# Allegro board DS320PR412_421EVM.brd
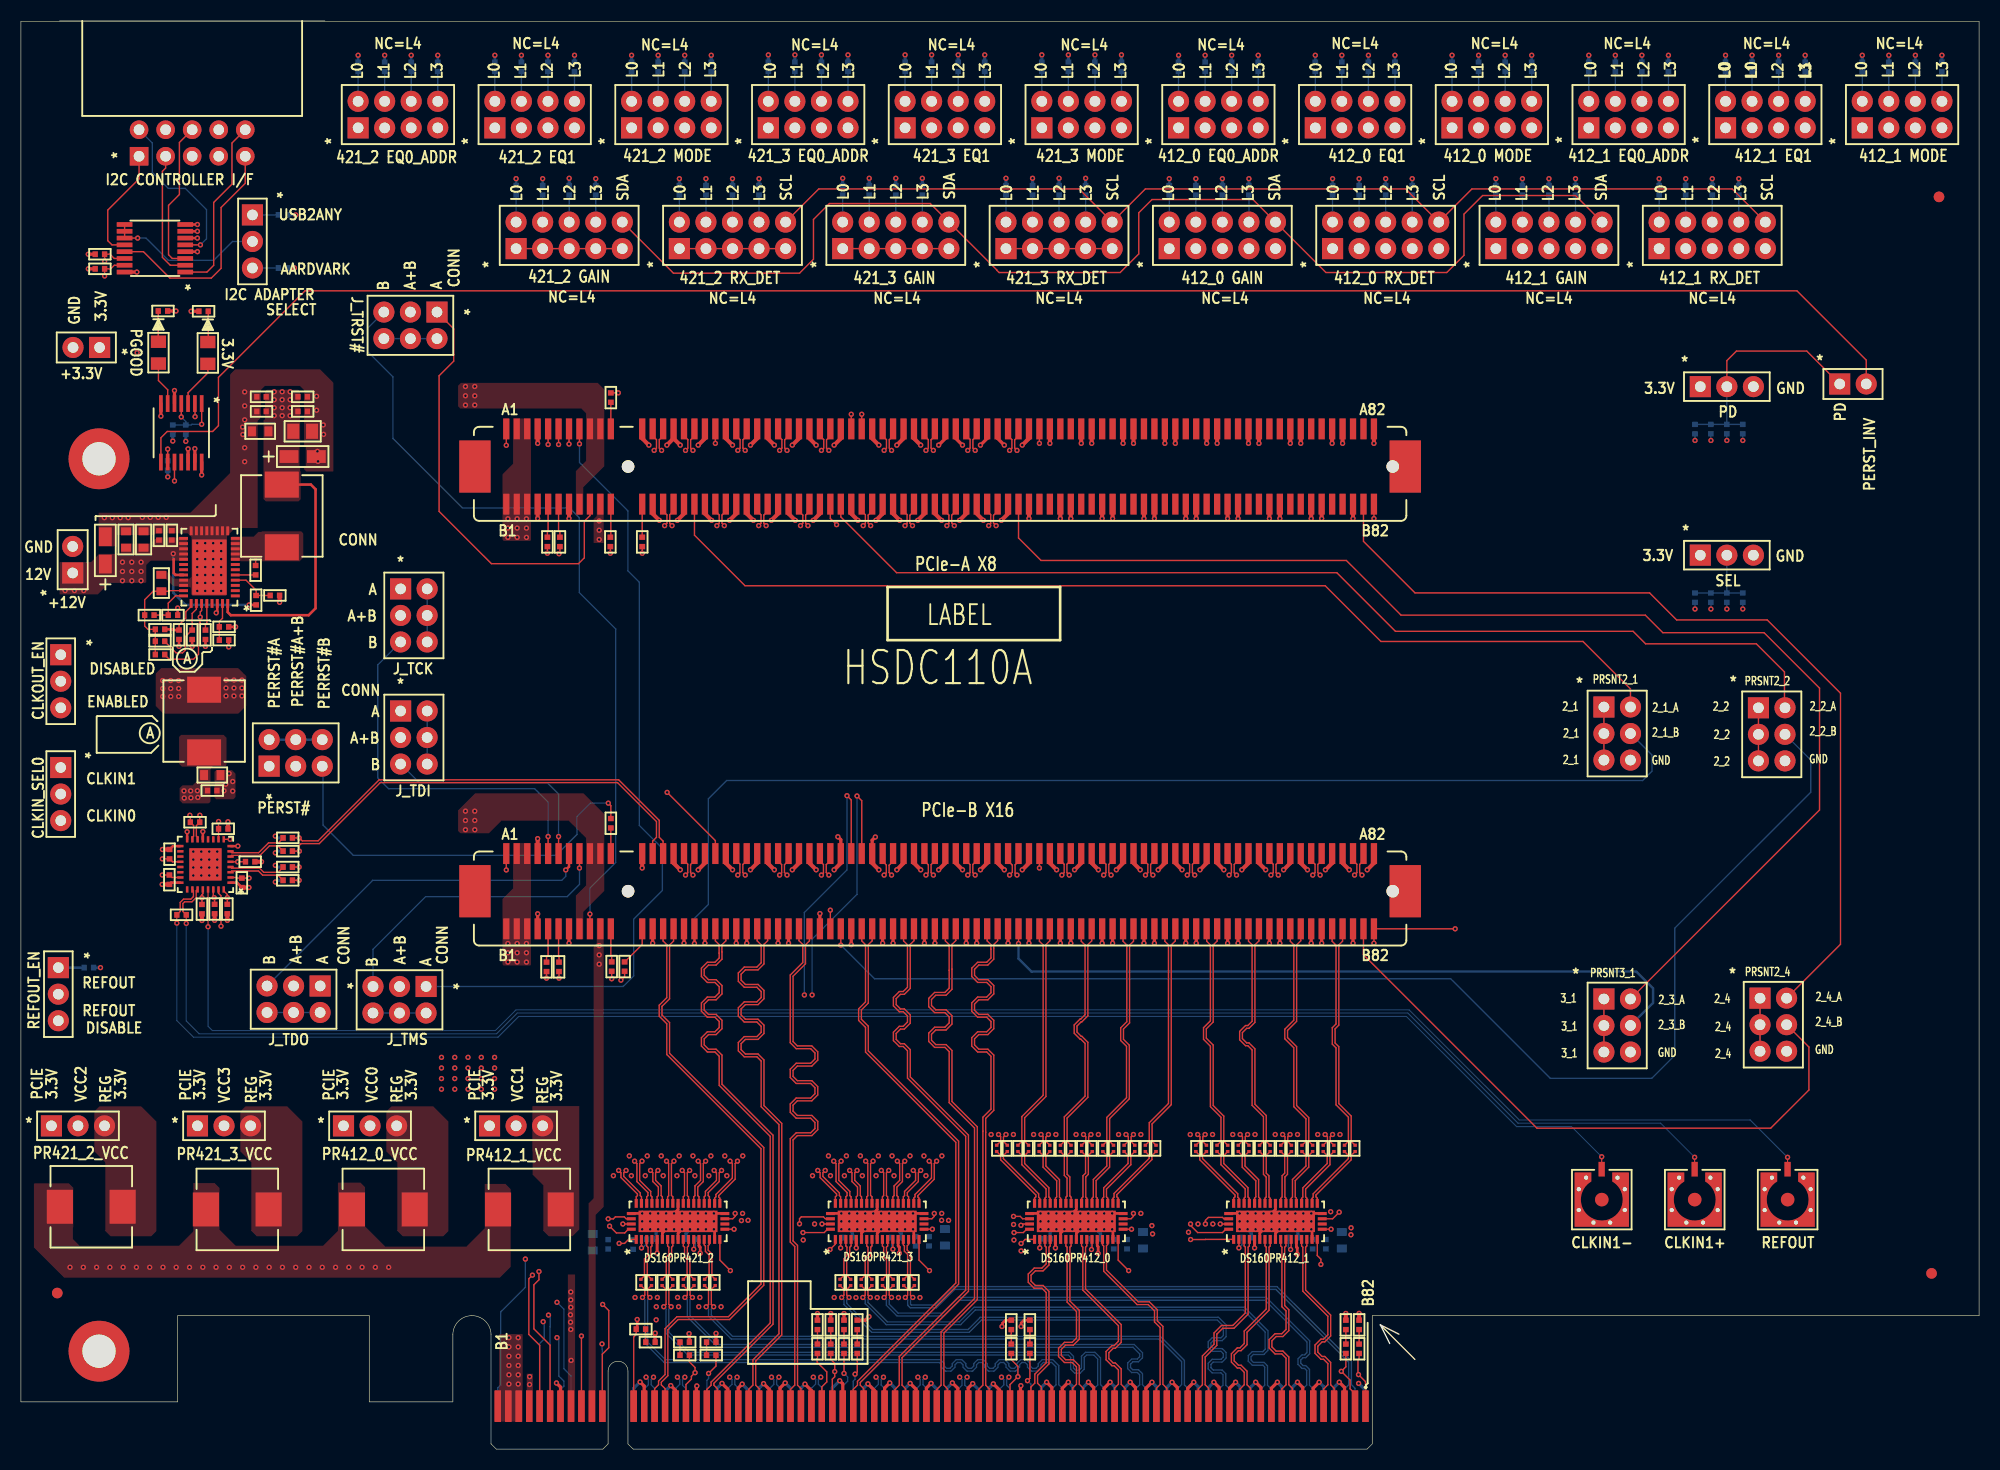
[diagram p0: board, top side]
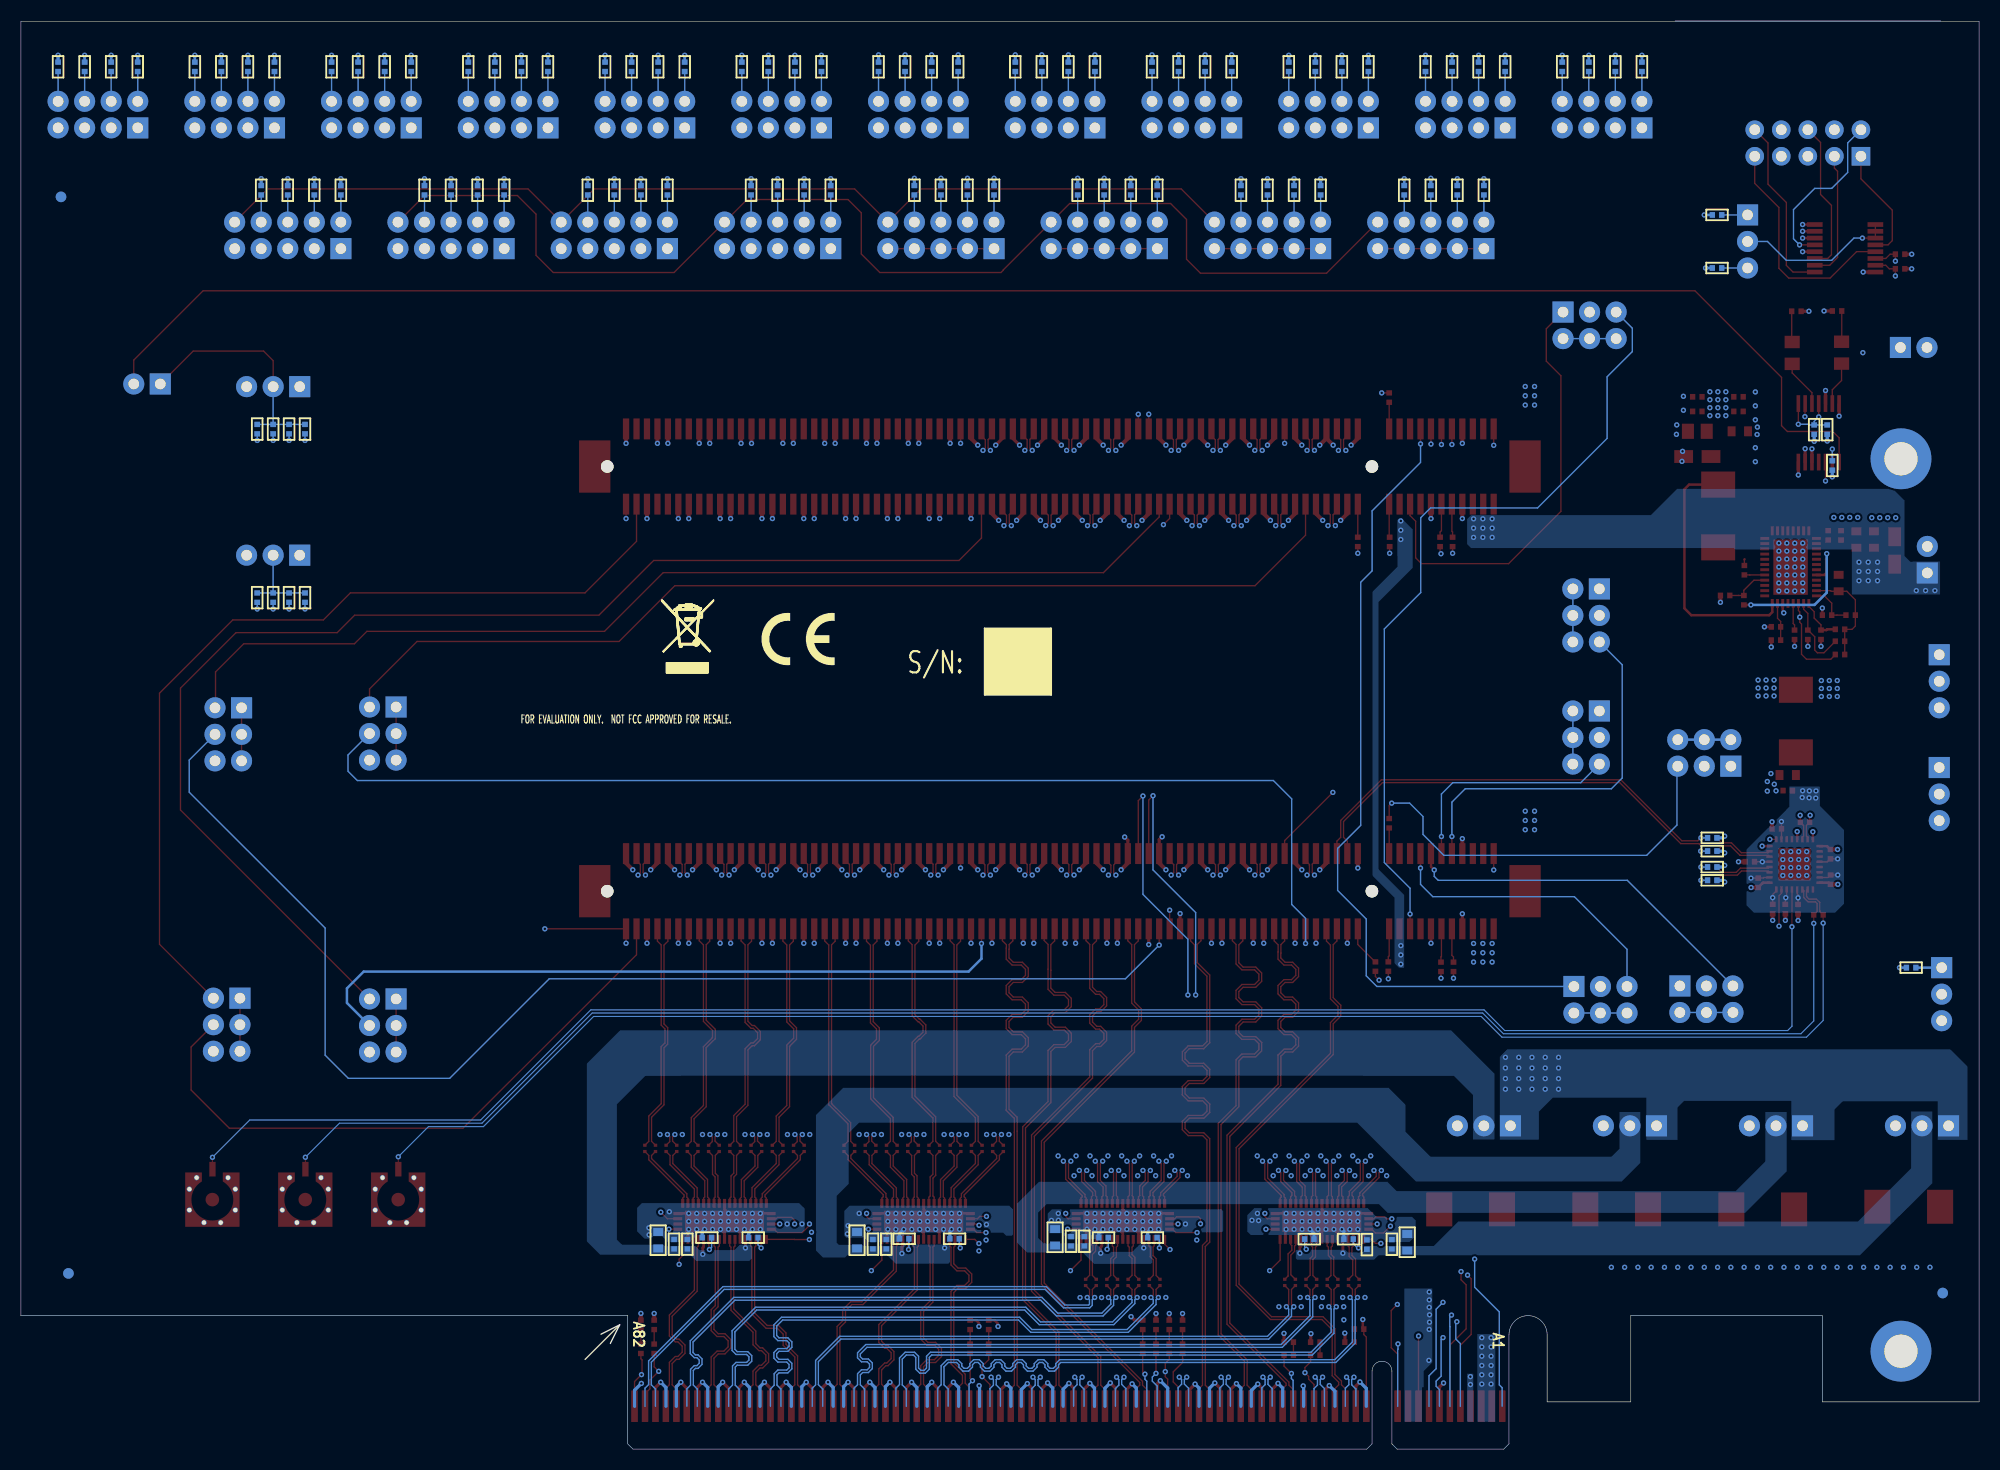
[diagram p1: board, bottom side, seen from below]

Outline 187.32 x 136.68 mm; copper layers: TOP, L2_GND, L3_SIG, L4_SIG, L5_GND, BOTTOM. Coordinates in mm from the lower left corner of the outline.
Outline path: 0,136.63 187.32,136.63 187.32,12.77 129.27,12.77 129.27,0.5 128.77,0 58.57,0 58.07,0.5 58.07,7.47 arc(57.12,8.42) 56.17,7.47 56.17,0.5 55.67,0 45.47,0 44.97,0.5 44.97,10.95 arc(44.44,12.24) 43.15,12.77 arc(41.86,12.24) 41.32,10.95 41.32,4.52 33.32,4.52 33.32,12.77 15,12.77 15,4.52 0,4.52 0,136.63

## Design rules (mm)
constraint set DEFAULT: min track width 0.102
net group DIFFPAIR3: nets PET9_N_B PET9_P_B
net group DIFFPAIR4: nets PER8_N PER8_P
net group DIFFPAIR5: nets PER9_N PER9_P
net group DIFFPAIR6: nets PER10_N PER10_P
net group DIFFPAIR7: nets PER11_N PER11_P
net group DIFFPAIR8: nets PER12_N PER12_P
net group DIFFPAIR9: nets PER13_N PER13_P
net group DIFFPAIR10: nets PER14_N PER14_P
net group DIFFPAIR11: nets PER15_N PER15_P
net group DIFFPAIR12: nets N16641538 N16641618
net group DIFFPAIR13: nets N16641774 N16641854
net group DIFFPAIR14: nets N16641982 N16642062
net group DIFFPAIR15: nets N16642250 N16642330
net group DIFFPAIR16: nets N16641526 N16641606
net group DIFFPAIR17: nets N16641762 N16641842
net group DIFFPAIR18: nets N16641970 N16642050
net group DIFFPAIR19: nets N16642238 N16642318
net group DIFFPAIR20: nets N16637226 N16637298
net group DIFFPAIR21: nets N16637382 N16637494
net group DIFFPAIR22: nets N16637572 N16637646
net group DIFFPAIR23: nets N16637738 N16637818
net group DIFFPAIR24: nets N16637946 N16638026
net group DIFFPAIR25: nets N16638098 N16638172
net group DIFFPAIR26: nets N16638286 N16638374
net group DIFFPAIR27: nets N16638446 N16638538
net group DIFFPAIR28: nets N16637238 N16637314
net group DIFFPAIR29: nets N16637394 N16637506
net group DIFFPAIR30: nets N16637586 N16637662
net group DIFFPAIR31: nets N16637750 N16637830
net group DIFFPAIR32: nets N16637958 N16638038
net group DIFFPAIR33: nets N16638114 N16638186
net group DIFFPAIR34: nets N16638298 N16638386
net group DIFFPAIR35: nets N16638462 N16638550
net group PET0_A: nets PET0_N_A PET0_P_A
net group PET1_A: nets PET1_N_A PET1_P_A
net group PET2_A: nets PET2_N_A PET2_P_A
net group PET3_A: nets PET3_N_A PET3_P_A
net group PET4_A: nets PET4_N_A PET4_P_A
net group PET5_A: nets PET5_N_A PET5_P_A
net group PET6_A: nets PET6_N_A PET6_P_A
net group PET7_A: nets PET7_N_A PET7_P_A
net group PET8_B: nets PET8_N_B PET8_P_B
net group PET10_B: nets PET10_N_B PET10_P_B
net group PET11_B: nets PET11_N_B PET11_P_B
net group PET12_B: nets PET12_N_B PET12_P_B
net group PET13_B: nets PET13_N_B PET13_P_B
net group PET14_B: nets PET14_N_B PET14_P_B
net group PET15_B: nets PET15_N_B PET15_P_B

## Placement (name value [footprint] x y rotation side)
C1  0.1uF  [CAP_0402]  98.01 20.13 180 bottom
C2  0.1uF  [CAP_0402]  102.83 20.13 180 bottom
C3  0.22uF  [CAP_0201]  93.34 28.78 90 top
C4  0.22uF  [CAP_0201]  94.36 28.78 90 top
C5  0.22uF  [CAP_0201]  95.38 28.78 90 top
C6  0.22uF  [CAP_0201]  96.39 28.78 90 top
C7  0.22uF  [CAP_0201]  97.41 28.78 90 top
C8  0.22uF  [CAP_0201]  98.42 28.78 90 top
C9  0.22uF  [CAP_0201]  99.44 28.78 90 top
C10  0.22uF  [CAP_0201]  100.46 28.78 90 top
C11  0.22uF  [CAP_0201]  101.47 28.78 90 top
C12  0.22uF  [CAP_0201]  102.49 28.78 90 top
C13  0.22uF  [CAP_0201]  103.5 28.78 90 top
C14  0.22uF  [CAP_0201]  104.52 28.78 90 top
C15  0.22uF  [CAP_0201]  105.54 28.78 90 top
C16  0.22uF  [CAP_0201]  106.55 28.78 90 top
C17  0.22uF  [CAP_0201]  107.57 28.78 90 top
C18  0.22uF  [CAP_0201]  108.58 28.78 90 top
C19  0.22uF  [CAP_0201]  112.39 28.78 90 top
C20  0.22uF  [CAP_0201]  113.41 28.78 90 top
C21  0.22uF  [CAP_0201]  114.43 28.78 90 top
C22  0.1uF  [CAP_0402]  117.26 20.24 180 bottom
C23  0.22uF  [CAP_0201]  115.44 28.78 90 top
C24  0.22uF  [CAP_0201]  116.46 28.78 90 top
C25  0.22uF  [CAP_0201]  117.47 28.78 90 top
C26  0.22uF  [CAP_0201]  118.49 28.78 90 top
C27  0.22uF  [CAP_0201]  119.51 28.78 90 top
C28  0.22uF  [CAP_0201]  120.52 28.78 90 top
C29  0.22uF  [CAP_0201]  121.54 28.78 90 top
C30  0.22uF  [CAP_0201]  122.56 28.78 90 top
C31  0.22uF  [CAP_0201]  123.57 28.78 90 top
C32  0.1uF  [CAP_0402]  121.7 20.24 180 bottom
C33  0.22uF  [CAP_0201]  124.59 28.78 90 top
C34  0.22uF  [CAP_0201]  125.6 28.78 90 top
C35  0.22uF  [CAP_0201]  126.62 28.78 90 top
C36  0.22uF  [CAP_0201]  127.64 28.78 90 top
C37  10uF  [CAP_0603]  107.34 19.99 270 bottom
C38  0.1uF  [CAP_0402]  104.55 19.61 270 bottom
C39  0.1uF  [CAP_0402]  105.82 19.61 270 bottom
C40  10uF  [CAP_0603]  126.36 19.99 270 bottom
C41  0.1uF  [CAP_0402]  123.57 19.61 270 bottom
C42  0.1uF  [CAP_0402]  124.84 19.61 270 bottom
C43  0.1uF  [CAP_0402]  60.32 20.09 0 bottom
C44  0.22uF  [CAP_0201]  59.31 15.95 90 top
C45  0.22uF  [CAP_0201]  60.33 15.95 90 top
C46  0.22uF  [CAP_0201]  61.34 15.95 90 top
C47  0.22uF  [CAP_0201]  62.36 15.95 90 top
C48  0.22uF  [CAP_0201]  63.37 15.95 90 top
C49  0.22uF  [CAP_0201]  64.39 15.95 90 top
C50  0.1uF  [CAP_0402]  64.07 20.09 180 bottom
C51  0.22uF  [CAP_0201]  65.41 15.95 90 top
C52  0.22uF  [CAP_0201]  66.42 15.95 90 top
C53  0.1uF  [CAP_0402]  79.09 20.24 0 bottom
C54  0.22uF  [CAP_0201]  78.36 15.95 90 top
C55  0.22uF  [CAP_0201]  79.38 15.95 90 top
C56  0.22uF  [CAP_0201]  80.39 15.95 90 top
C57  0.22uF  [CAP_0201]  81.41 15.95 90 top
C58  0.22uF  [CAP_0201]  82.42 15.95 90 top
C59  0.22uF  [CAP_0201]  83.44 15.95 90 top
C60  0.1uF  [CAP_0402]  83.76 20.24 0 bottom
C61  0.22uF  [CAP_0201]  84.45 15.95 90 top
C62  0.22uF  [CAP_0201]  85.47 15.95 90 top
C63  10uF  [CAP_0603]  54.71 19.8 270 bottom
C64  0.1uF  [CAP_0402]  58.56 19.57 270 bottom
C65  0.1uF  [CAP_0402]  56.17 19.6 270 bottom
C66  10uF  [CAP_0603]  88.39 20.27 270 bottom
C67  0.1uF  [CAP_0402]  86.87 19.89 270 bottom
C68  0.1uF  [CAP_0402]  85.6 19.89 270 bottom
C69  0.1uF  [CAP_0402]  22.45 84.11 90 top
C70  100uF  [TANT_3216-18]  26.95 94.99 0 top
C71  47uF  [CAP_0805]  26.95 97.4 180 top
C72  10uF  [CAP_0603]  22.89 97.4 0 top
C73  4.7uF  [CAP_0402]  23.02 99.31 0 top
C74  1uF  [CAP_0402]  26.95 99.31 180 top
C75  0.47uF  [CAP_0402]  26.95 100.7 180 top
C76  0.1uF  [CAP_0402]  23.02 100.7 0 top
C78  1uF  [CAP_0402]  14.44 87.44 270 top
C79  4.7uF  [CAP_0402]  13.21 87.44 270 top
C80  22uF  [CAP_0603]  11.73 87.05 270 top
C81  100uF  [TANT_3216-18]  8.08 86 90 top
C82  22uF  [CAP_0603]  10.06 87.05 270 top
C83  1pF  [CAP_0402]  59.31 11.48 0 top
C84  1pF  [CAP_0402]  128.02 9.6 90 top
C85  1pF  [CAP_0402]  66.04 8.99 180 top
C86  1pF  [CAP_0402]  76.2 9.6 90 top
C87  1pF  [CAP_0402]  78.74 9.6 90 top
C88  1pF  [CAP_0402]  80.01 9.6 90 top
C89  1pF  [CAP_0402]  96.52 9.6 90 top
C90  1pF  [CAP_0402]  63.5 8.99 180 top
C91  1pF  [CAP_0402]  77.47 9.6 90 top
C92  1pF  [CAP_0402]  94.74 9.6 90 top
C93  1pF  [CAP_0402]  126.75 9.6 90 top
C94  0.1uF  [CAP_0402]  14.22 56.93 270 top
C95  0.1uF  [CAP_0402]  14.2 54.49 90 top
C96  0.1uF  [CAP_0402]  17.32 51.67 90 top
C97  0.1uF  [CAP_0402]  18.53 51.69 90 top
C98  0.1uF  [CAP_0402]  19.75 51.69 90 top
C99  0.1uF  [CAP_0402]  21.14 54.19 90 top
C100  0.1uF  [CAP_0402]  21.93 56.21 180 top
C101  0.1uF  [CAP_0402]  19.36 59.36 180 top
C102  1uF  [CAP_0402]  18.3 63.02 180 top
C103  10uF  [CAP_0603]  18.31 64.51 180 top
C104  10uF  [CAP_0603]  13.44 82.88 270 top
C105  1uF  [CAP_0402]  14.53 97.56 270 bottom
D1  LED Green 0805  [LED_0805]  17.88 104.9 270 top
D2  LED Green 0805  [LED_0805]  13.16 104.93 270 top
J1  HDR3X1 M .1  [HDR_THVT_1X3_254_838]  33.4 30.94 0 top
J2  HDR3X1 M .1  [HDR_THVT_1X3_254_838]  47.37 30.94 0 top
J3  HDR3X1 M .1  [HDR_THVT_1X3_254_838]  5.46 30.94 0 top
J4  HDR3X1 M .1  [HDR_THVT_1X3_254_838]  19.43 30.94 0 top
J5  HDR3X2 .1X.1  [HDR_THVT_2X3_254_871]  39.8 108.81 270 top
J6  HDR3X2 .1X.1  [HDR_THVT_2X3_254_871]  36.32 82.32 0 top
J7  HDR3X2 .1X.1  [HDR_THVT_2X3_254_871]  36.32 70.64 0 top
J8  HDR3X2 .1X.1  [HDR_THVT_2X3_254_871]  28.63 44.32 270 top
J9  HDR3X2 .1X.1  [HDR_THVT_2X3_254_871]  38.76 44.27 270 top
J10  HDR2X1 M .1  [HDR_THVT_1X2_254_871]  7.53 105.42 180 top
J11  HDR2X1 M .1  [HDR_THVT_1X2_254_871]  4.95 83.85 90 top
J12  SMP  [CON_SMVT_19S101-40ML5_R04350]  169.01 23.88 180 top
J13  SMP  [CON_SMVT_19S101-40ML5_R04350]  160.12 23.88 180 top
J14  SMP  [CON_SMVT_19S101-40ML5_R04350]  151.23 23.88 180 top
J15  10146070-113Y0LF  [CON_SMVT_10146070-113Y0LF]  87.93 94.03 0 top
J16  10146070-113Y0LF  [CON_SMVT_10146070-113Y0LF]  87.93 53.39 0 top
J17  HDR3X2 .1X.1  [HDR_THVT_2X3_254_871]  23.75 65.35 90 top
J18  HDR3X2 .1X.1  [HDR_THVT_2X3_254_871]  151.43 71.02 0 top
J19  HDR3X2 .1X.1  [HDR_THVT_2X3_254_871]  166.22 70.94 0 top
J20  HDR3X2 .1X.1  [HDR_THVT_2X3_254_871]  151.43 43.08 0 top
J21  HDR3X2 .1X.1  [HDR_THVT_2X3_254_871]  166.37 43.15 0 top
J22  HDR2X1 M .1  [HDR_THVT_1X2_254_871]  173.99 101.93 0 top
J23  HDR5X2 .1X.1  [HDR_THVT_2X5_254_838]  109.86 114.88 90 top
J24  HDR5X2 .1X.1  [HDR_THVT_2X5_254_838]  156.72 114.88 90 top
J25  HDR5X2 .1X.1  [HDR_THVT_2X5_254_838]  141.1 114.88 90 top
J26  HDR5X2 .1X.1  [HDR_THVT_2X5_254_838]  62.99 114.88 90 top
J27  HDR5X2 .1X.1  [HDR_THVT_2X5_254_838]  47.37 114.88 90 top
J28  HDR5X2 .1X.1  [HDR_THVT_2X5_254_838]  94.23 114.88 90 top
J29  HDR5X2 .1X.1  [HDR_THVT_2X5_254_838]  78.61 114.88 90 top
J30  HDR5X2 .1X.1  [HDR_THVT_2X5_254_838]  125.48 114.88 90 top
JMP1  Header 4x2  [HDR_THVT_2X4_254_871]  110.74 126.44 90 top
JMP2  Header 4x2  [HDR_THVT_2X4_254_871]  123.83 126.44 90 top
JMP3  Header 4x2  [HDR_THVT_2X4_254_871]  136.91 126.44 90 top
JMP4  Header 4x2  [HDR_THVT_2X4_254_871]  149.99 126.44 90 top
JMP5  Header 4x2  [HDR_THVT_2X4_254_871]  163.07 126.44 90 top
JMP6  Header 4x2  [HDR_THVT_2X4_254_871]  176.15 126.44 90 top
JMP7  Header 3x1  [HDR_THVT_1X3_254_871]  163.19 85.55 0 top
JMP8  Header 3x1  [HDR_THVT_1X3_254_871]  163.19 101.68 0 top
JMP9  Header 4x2  [HDR_THVT_2X4_254_871]  32.26 126.44 90 top
JMP10  Header 4x2  [HDR_THVT_2X4_254_871]  45.34 126.44 90 top
JMP11  Header 4x2  [HDR_THVT_2X4_254_871]  58.42 126.44 90 top
JMP14  Header 4x2  [HDR_THVT_2X4_254_871]  71.5 126.44 90 top
JMP15  Header 4x2  [HDR_THVT_2X4_254_871]  84.58 126.44 90 top
JMP16  Header 4x2  [HDR_THVT_2X4_254_871]  97.66 126.44 90 top
JMP17  Header 3x1  [HDR_THVT_1X3_254_871]  22.15 115.57 270 top
JMP18  Header 3x1  [HDR_THVT_1X3_254_871]  3.81 73.48 270 top
JMP19  Header 3x1  [HDR_THVT_1X3_254_871]  3.81 62.69 270 top
JMP20  Header 3x1  [HDR_THVT_1X3_254_871]  3.58 43.54 270 top
L1  6.8uH  [IND_SM_DRA73]  34.67 22.94 0 top
L2  6.8uH  [IND_SM_DRA73]  48.64 22.94 0 top
L3  6.8uH  [IND_SM_DRA73]  6.73 23.19 0 top
L4  6.8uH  [IND_SM_DRA73]  20.7 22.94 0 top
L5  6.8uH  [IND_SM_DRA73]  24.96 89.3 270 top
L6  6.8uH  [IND_SM_DRA73]  17.53 69.67 90 top
NOREF  -  []  187.32 12.77 90 top
NOREF#2  -  []  0 4.52 0 top
NOREF#3  -  []  140.36 70.43 0 top
NOREF#4  -  []  272.77 94.26 0 top
NOREF#5  -  [unnamed#2]  3.48 14.93 0 top
NOREF#6  -  []  272.77 122.84 0 top
NOREF#7  -  [unnamed#2]  183.49 119.84 0 top
NOREF#8  -  []  74.57 64.57 0 top
NOREF#9  -  []  88.9 42.62 0 top
NOREF#10  -  []  135.99 77.14 0 top
NOREF#11  -  []  -3.81 -65.33 0 top
NOREF#12  -  [unnamed#2]  182.78 16.81 0 top
NOREF#13  -  []  0 136.63 0 top
NOREF#14  -  []  340.71 122.84 0 top
NOREF#15  -  []  112.98 77.52 180 bottom
NOREF#16  -  [unnamed#2]  183.49 119.84 180 bottom
NOREF#17  -  [unnamed#2]  182.78 16.81 180 bottom
NOREF#18  -  []  123.52 78.31 180 bottom
NOREF#19  -  [unnamed#2]  3.48 14.93 180 bottom
NOREF#20  -  []  102.11 75.36 180 bottom
P4  Header 5x2 0.1" Shroud RA thru-hole  [CON_SHRD_THRT_30310-5002HB]  16.38 126.26 90 top
P5  PCIe Gen 5 Edge Connector  [CON_EDGE_164_100_GEN5]  0 4.52 0 top
R1  1K  [RES_0402]  110.74 132.28 270 bottom
R2  8.25K  [RES_0402]  113.28 132.28 270 bottom
R3  24.9K  [RES_0402]  115.82 132.28 90 bottom
R4  75K  [RES_0402]  118.36 132.28 270 bottom
R5  1K  [RES_0402]  123.83 132.28 270 bottom
R6  8.25K  [RES_0402]  126.36 132.28 270 bottom
R7  24.9K  [RES_0402]  128.91 132.28 90 bottom
R8  75K  [RES_0402]  131.44 132.28 270 bottom
R9  1K  [RES_0402]  136.91 132.28 270 bottom
R10  8.25K  [RES_0402]  139.45 132.28 270 bottom
R11  24.9K  [RES_0402]  141.99 132.28 90 bottom
R12  75K  [RES_0402]  144.53 132.28 270 bottom
R13  1K  [RES_0402]  125.48 120.47 270 bottom
R14  8.25K  [RES_0402]  128.02 120.47 270 bottom
R15  24.9K  [RES_0402]  130.56 120.47 90 bottom
R16  75K  [RES_0402]  133.1 120.47 270 bottom
R17  1K  [RES_0402]  109.86 120.47 270 bottom
R18  8.25K  [RES_0402]  112.39 120.47 270 bottom
R19  24.9K  [RES_0402]  114.94 120.47 90 bottom
R20  75K  [RES_0402]  117.47 120.47 270 bottom
R21  1K  [RES_0402]  149.99 132.28 270 bottom
R22  8.25K  [RES_0402]  152.53 132.28 270 bottom
R23  24.9K  [RES_0402]  155.07 132.28 90 bottom
R24  75K  [RES_0402]  157.61 132.28 270 bottom
R25  1K  [RES_0402]  163.07 132.28 270 bottom
R26  8.25K  [RES_0402]  165.61 132.28 270 bottom
R27  24.9K  [RES_0402]  168.15 132.28 90 bottom
R28  75K  [RES_0402]  170.69 132.28 270 bottom
R29  1K  [RES_0402]  176.15 132.28 270 bottom
R30  8.25K  [RES_0402]  178.69 132.28 270 bottom
R31  1K  [RES_0402]  161.67 81.48 270 bottom
R32  1K  [RES_0402]  160.15 81.48 270 bottom
R33  1K  [RES_0402]  164.72 81.48 270 bottom
R34  1K  [RES_0402]  163.19 81.48 270 bottom
R35  1K  [RES_0402]  161.67 97.61 270 bottom
R36  1K  [RES_0402]  160.15 97.61 270 bottom
R37  1K  [RES_0402]  164.72 97.61 270 bottom
R38  1K  [RES_0402]  163.19 97.61 270 bottom
R39  24.9K  [RES_0402]  181.23 132.28 90 bottom
R40  75K  [RES_0402]  183.77 132.28 270 bottom
R41  1K  [RES_0402]  156.72 120.47 270 bottom
R42  8.25K  [RES_0402]  159.26 120.47 270 bottom
R43  24.9K  [RES_0402]  161.8 120.47 90 bottom
R44  75K  [RES_0402]  164.34 120.47 270 bottom
R45  1K  [RES_0402]  141.1 120.47 270 bottom
R46  8.25K  [RES_0402]  143.64 120.47 270 bottom
R47  24.9K  [RES_0402]  146.18 120.47 90 bottom
R48  75K  [RES_0402]  148.72 120.47 270 bottom
R49  1K  [RES_0402]  32.26 132.28 270 bottom
R50  8.25K  [RES_0402]  34.8 132.28 270 bottom
R51  24.9K  [RES_0402]  37.34 132.28 90 bottom
R52  75K  [RES_0402]  39.88 132.28 270 bottom
R53  1K  [RES_0402]  45.34 132.28 270 bottom
R62  8.25K  [RES_0402]  47.88 132.28 270 bottom
R63  24.9K  [RES_0402]  50.42 132.28 90 bottom
R64  75K  [RES_0402]  52.96 132.28 270 bottom
R65  1K  [RES_0402]  58.42 132.28 270 bottom
R66  8.25K  [RES_0402]  60.96 132.28 270 bottom
R67  24.9K  [RES_0402]  63.5 132.28 90 bottom
R68  75K  [RES_0402]  66.04 132.28 270 bottom
R69  1K  [RES_0402]  62.99 120.47 270 bottom
R70  8.25K  [RES_0402]  65.53 120.47 270 bottom
R71  24.9K  [RES_0402]  68.07 120.47 90 bottom
R72  75K  [RES_0402]  70.61 120.47 270 bottom
R73  1K  [RES_0402]  47.37 120.47 270 bottom
R74  8.25K  [RES_0402]  49.91 120.47 270 bottom
R75  24.9K  [RES_0402]  52.45 120.47 90 bottom
R76  75K  [RES_0402]  54.99 120.47 270 bottom
R77  1K  [RES_0402]  25.07 118.11 0 bottom
R78  1K  [RES_0402]  25.07 113.03 0 bottom
R79  4.7K  [RES_0402]  7.56 114.35 0 top
R80  4.7K  [RES_0402]  7.56 112.95 0 top
R81  165K  [RES_0402]  22.5 81.24 90 top
R82  121K  [RES_0402]  24.3 81.69 0 top
R83  330  [RES_0402]  17.48 108.89 0 top
R84  37.4K  [RES_0402]  14.55 79.81 180 top
R85  100K  [RES_0402]  12.29 79.81 0 top
R86  100K  [RES_0402]  13.31 78.45 0 top
R87  100K  [RES_0402]  13.31 77.31 0 top
R88  165K  [RES_0402]  15.13 77.93 270 top
R89  42.2K  [RES_0402]  16.38 77.93 270 top
R90  105K  [RES_0402]  13.31 76.04 0 top
R91  205K  [RES_0402]  17.65 77.93 90 top
R92  5.76K  [RES_0402]  19.43 77.42 180 top
R93  10K  [RES_0402]  19.43 78.69 0 top
R94  330  [RES_0402]  13.59 108.91 180 top
R95  43  [RES_0402]  60.22 10.24 0 top
R96  43  [RES_0402]  128.02 11.89 90 top
R97  43  [RES_0402]  66.04 10.24 0 top
R98  43  [RES_0402]  76.2 11.89 90 top
R99  43  [RES_0402]  78.74 11.89 90 top
R100  43  [RES_0402]  80.01 11.89 90 top
R101  43  [RES_0402]  96.52 11.89 90 top
R102  43  [RES_0402]  63.5 10.24 0 top
R103  43  [RES_0402]  77.47 11.89 90 top
R104  43  [RES_0402]  94.74 11.89 90 top
R105  43  [RES_0402]  126.75 11.89 90 top
R106  49.9  [RES_0402]  25.53 54.43 180 bottom
R107  33  [RES_0402]  25.53 54.43 180 top
R108  33  [RES_0402]  25.53 55.7 180 top
R109  33  [RES_0402]  25.53 57.23 180 top
R110  33  [RES_0402]  25.53 58.5 180 top
R115  49.9  [RES_0402]  25.53 55.7 180 bottom
R116  49.9  [RES_0402]  25.53 57.23 180 bottom
R117  49.9  [RES_0402]  25.53 58.5 180 bottom
R118  100 DNI  [RES_0402]  15.37 51.13 180 top
R119  100 DNI  [RES_0402]  16.66 59.99 180 top
R120  1K  [RES_0402]  6.5 46.08 180 bottom
R121  1  [RES_0402]  56.43 100.63 90 top
R122  1  [RES_0402]  50.37 86.82 90 top
R123  1  [RES_0402]  51.56 86.82 90 top
R124  1  [RES_0402]  56.39 86.82 90 top
R125  1  [RES_0402]  59.44 86.82 90 top
R126  1  [RES_0402]  50.28 46.15 90 top
R127  1  [RES_0402]  51.48 46.15 90 top
R128  1  [RES_0402]  56.43 59.89 90 top
R129  1  [RES_0402]  56.52 46.18 90 top
R130  1  [RES_0402]  57.75 46.18 90 top
R131  10K  [RES_0402]  14.05 94.13 90 bottom
R132  10K  [RES_0402]  15.77 97.56 270 bottom
R133  1K  [RES_0402]  71.5 132.28 270 bottom
R134  8.25K  [RES_0402]  74.04 132.28 270 bottom
R135  24.9K  [RES_0402]  76.58 132.28 90 bottom
R136  75K  [RES_0402]  79.12 132.28 270 bottom
R137  1K  [RES_0402]  84.58 132.28 270 bottom
R138  8.25K  [RES_0402]  87.12 132.28 270 bottom
R139  24.9K  [RES_0402]  89.66 132.28 90 bottom
R140  75K  [RES_0402]  92.2 132.28 270 bottom
R141  1K  [RES_0402]  97.66 132.28 270 bottom
R142  8.25K  [RES_0402]  100.2 132.28 270 bottom
R143  24.9K  [RES_0402]  102.74 132.28 90 bottom
R144  75K  [RES_0402]  105.28 132.28 270 bottom
R145  1K  [RES_0402]  94.23 120.47 270 bottom
R146  8.25K  [RES_0402]  96.77 120.47 270 bottom
R147  24.9K  [RES_0402]  99.31 120.47 90 bottom
R148  75K  [RES_0402]  101.85 120.47 270 bottom
R149  1K  [RES_0402]  78.61 120.47 270 bottom
R150  8.25K  [RES_0402]  81.15 120.47 270 bottom
R151  24.9K  [RES_0402]  83.69 120.47 90 bottom
R152  75K  [RES_0402]  86.23 120.47 270 bottom
U1  DS320PR412  [RUA0042BA_205X755]  100.97 21.79 90 top
U2  DS320PR412  [RUA0042BA_205X755]  120.02 21.79 90 top
U3  DS320PR421  [RUA0042BA_205X755]  62.87 21.79 90 top
U4  DS320PR421  [RUA0042BA_205X755]  81.92 21.79 90 top
U5  TMUX1133PWR  [PW0016AB]  12.82 114.92 180 top
U6  TPS548B22RVFT  [RVF0040BA_330X530]  18.03 84.4 180 top
U7  SN74LVC125A_PW_14  [PW0014AA]  15.34 97.26 270 top
U8  LMK00334RTVR  [RTV0032BA_310X310]  17.65 55.96 180 top

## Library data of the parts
C1 C2 C22 C32 C43 C50 C53 C60 = GRM155R71A104KA01J: signal model: GRM155R61A224KE19J_0_CAP_0402_0_0.22uF
C3-C21 C23-C31 C33-C36 C44-C49 C51 C52 C54-C59 C61 C62 = C0603X5R0J224K030BB: signal model: GRM155R61A224KE19J_0_CAP_0402_0_0.22uF
C37 C40 C63 C66 C103 = GRM188R60J106ME47D
C38 C39 C41 C42 C64 C65 C67-C69 C76 C94-C101 = GRM155R71A104KA01J
C70 C81 = T520A107M006ATE070
C71 = JMK212BJ476MG-T
C72 C104 = GRM188R61A106KE69D
C73 C79 = GRM155R60J475ME47D
C74 C78 C102 C105 = CC0402KRX5R6BB105
C75 = GRM155R60J474KE19D
C80 C82 = C0603C224K8NACTU
C83-C93 = GRM1555C1H1R0CA01D
D1 D2 = LED Green 0805_0
J1-J4 = HDR3X1 M .1
J5-J9 J17-J21 = HDR3X2 M .1X.1
J10 J11 J22 = HDR2X1 M .1
J12-J14 = SMP_0
J15 J16 = PCIe GEN 5 x16 SMT CEM_1
J23-J30 = HDR5X2 M .1X.1
JMP1-JMP6 JMP9-JMP11 JMP14-JMP16 = Header 4x2
JMP7 JMP8 JMP17-JMP20 = Header 3x1
L1-L6 = L_8A
P4 = CONN PCB 5x2-S
P5 = PCIe Gen 5 Edge Connector_2
R1 R5 R9 R13 R17 R21 R25 R29 R41 R45 R49 R53 R65 R69 R73 R133 R137 R141 R145 R149 = ERJ-2GEJ102X_0
R2 R6 R10 R14 R18 R22 R26 R30 R42 R46 R50 R62 R66 R70 R74 R134 R138 R142 R146 R150 = ERJ-2RKF8251X_0
R3 R7 R11 R15 R19 R23 R27 R39 R43 R47 R51 R63 R67 R71 R75 R135 R139 R143 R147 R151 = ERA-2AEB2492X_0
R4 R8 R12 R16 R20 R24 R28 R40 R44 R48 R52 R64 R68 R72 R76 R136 R140 R144 R148 R152 = ERA-2AED753X_0
R31-R38 R77 R78 R120 = ERJ-2GEJ102X_1
R79 R80 = ERJ-2GEJ472X_0
R81 = ERJ-2RKF1653X_0
R82 = RC0402FR-07121KL_0
R83 R94 = ERA-2AEB331X_0
R84 = ERJ-2RKF3742X_0
R85-R87 = ERJ-2GEJ104X_0
R88 = ERJ-2RKF1653X_1
R89 = ERJ-2RKF4222X_0
R90 = ERJ-2RKF1053X_0
R91 = ERJ-2RKF2053X_0
R92 = ERJ-2RKF5761X_0
R93 R131 R132 = ERA-2AED103X_0
R95-R105 = r0402
R106 R115-R117 = ERJ-2RKF49R9X_0
R107-R110 = ERA-2AKD330X_0
R118 R119 = ERA-2AED101X_0
R121-R130 = RC0402FR-071RL_0
U1 U2 = DS320PR412_3
U3 U4 = DS320PR421_1
U5 = TMUX1133PWR
U6 = TPS548B22RVFT_1
U7 = SN74LVC125AQPWRQ1
U8 = LMK00334RTVR_0

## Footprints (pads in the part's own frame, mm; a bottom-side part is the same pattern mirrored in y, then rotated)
CAP_0201
  rect 0.3x0.33 smd: 1(-0.3,0) 2(0.3,0)
CAP_0402
  rect 0.51x0.55 smd: 1(-0.45,0) 2(0.45,0)
CAP_0603
  rect 0.76x0.95 smd: 1(-0.787,0) 2(0.787,0)
CAP_0805
  rect 1.15x1.45 smd: 1(-0.9,0) 2(0.9,0)
CON_EDGE_164_100_GEN5
  round 5.82 hole 3.175: (7.472,90.25) (7.472,4.85)
  rect 0.6x3 smd: A1(45.622,-0.421) A2(46.622,-0.421) A3(47.622,-0.421) A4(48.622,-0.421) A5(49.622,-0.421) A6(50.622,-0.421) A7(51.622,-0.421) A8(52.622,-0.421) A9(53.622,-0.421) A10(54.622,-0.421) A11(55.622,-0.421) A12(58.622,-0.421) A13(59.622,-0.421) A14(60.622,-0.421) A15(61.622,-0.421) A16(62.622,-0.421) A17(63.622,-0.421) A18(64.622,-0.421) A19(65.622,-0.421) A20(66.622,-0.421) A21(67.622,-0.421) A22(68.622,-0.421) A23(69.622,-0.421) A24(70.622,-0.421) A25(71.622,-0.421) A26(72.622,-0.421) A27(73.622,-0.421) A28(74.622,-0.421) A29(75.622,-0.421) A30(76.622,-0.421) A31(77.622,-0.421) A32(78.622,-0.421) A33(79.622,-0.421) A34(80.622,-0.421) A35(81.622,-0.421) A36(82.622,-0.421) A37(83.622,-0.421) A38(84.622,-0.421) A39(85.622,-0.421) A40(86.622,-0.421) A41(87.622,-0.421) A42(88.622,-0.421) A43(89.622,-0.421) A44(90.622,-0.421) A45(91.622,-0.421) A46(92.622,-0.421) A47(93.622,-0.421) A48(94.622,-0.421) A49(95.622,-0.421) A50(96.622,-0.421) A51(97.622,-0.421) A52(98.622,-0.421) A53(99.622,-0.421) A54(100.622,-0.421) A55(101.622,-0.421) A56(102.622,-0.421) A57(103.622,-0.421) A58(104.622,-0.421) A59(105.622,-0.421) A60(106.622,-0.421) A61(107.622,-0.421) A62(108.622,-0.421) A63(109.622,-0.421) A64(110.622,-0.421) A65(111.622,-0.421) A66(112.622,-0.421) A67(113.622,-0.421) A68(114.622,-0.421) A69(115.622,-0.421) A70(116.622,-0.421) A71(117.622,-0.421) A72(118.622,-0.421) A73(119.622,-0.421) A74(120.622,-0.421) A75(121.622,-0.421) A76(122.622,-0.421) A77(123.622,-0.421) A78(124.622,-0.421) A79(125.622,-0.421) A80(126.622,-0.421) A81(127.622,-0.421) A82(128.622,-0.421) B1(45.622,-0.421) B2(46.622,-0.421) B3(47.622,-0.421) B4(48.622,-0.421) B5(49.622,-0.421) B6(50.622,-0.421) B7(51.622,-0.421) B8(52.622,-0.421) B9(53.622,-0.421) B10(54.622,-0.421) B11(55.622,-0.421) B12(58.622,-0.421) B13(59.622,-0.421) B14(60.622,-0.421) B15(61.622,-0.421) B16(62.622,-0.421) B17(63.622,-0.421) B18(64.622,-0.421) B19(65.622,-0.421) B20(66.622,-0.421) B21(67.622,-0.421) B22(68.622,-0.421) B23(69.622,-0.421) B24(70.622,-0.421) B25(71.622,-0.421) B26(72.622,-0.421) B27(73.622,-0.421) B28(74.622,-0.421) B29(75.622,-0.421) B30(76.622,-0.421) B31(77.622,-0.421) B32(78.622,-0.421) B33(79.622,-0.421) B34(80.622,-0.421) B35(81.622,-0.421) B36(82.622,-0.421) B37(83.622,-0.421) B38(84.622,-0.421) B39(85.622,-0.421) B40(86.622,-0.421) B41(87.622,-0.421) B42(88.622,-0.421) B43(89.622,-0.421) B44(90.622,-0.421) B45(91.622,-0.421) B46(92.622,-0.421) B47(93.622,-0.421) B48(94.622,-0.421) B49(95.622,-0.421) B50(96.622,-0.421) B51(97.622,-0.421) B52(98.622,-0.421) B53(99.622,-0.421) B54(100.622,-0.421) B55(101.622,-0.421) B56(102.622,-0.421) B57(103.622,-0.421) B58(104.622,-0.421) B59(105.622,-0.421) B60(106.622,-0.421) B61(107.622,-0.421) B62(108.622,-0.421) B63(109.622,-0.421) B64(110.622,-0.421) B65(111.622,-0.421) B66(112.622,-0.421) B67(113.622,-0.421) B68(114.622,-0.421) B69(115.622,-0.421) B70(116.622,-0.421) B71(117.622,-0.421) B72(118.622,-0.421) B73(119.622,-0.421) B74(120.622,-0.421) B75(121.622,-0.421) B76(122.622,-0.421) B77(123.622,-0.421) B78(124.622,-0.421) B79(125.622,-0.421) B80(126.622,-0.421) B81(127.622,-0.421) B82(128.622,-0.421)
CON_SHRD_THRT_30310-5002HB
  rect 1.78x1.78 hole 1.02: 1(-2.54,5.08)
  round 1.78 hole 1.02: 2(0,5.08) 3(-2.54,2.54) 4(0,2.54) 5(-2.54,0) 6(0,0) 7(-2.54,-2.54) 8(0,-2.54) 9(-2.54,-5.08) 10(0,-5.08)
CON_SMVT_19S101-40ML5_R04350
  rect 0.6x1.4 smd: 1(0.01,-2.911)
  custom 1.3x1.3 smd: 2(0,0)
  round 0.508 hole 0.4: 3(0.8,2.2) 4(-0.8,2.2) 5(-2.2,1) 6(-2.2,-1) 7(-1.5,-2.1) 8(1.5,-2.1) 9(2.2,-1) 10(2.2,1)
CON_SMVT_10146070-113Y0LF
  rect 3x5 smd: (-44.5,0) (44.5,0)
  round 1.2 hole 1.2 unplated: (-29.85,0) (43.3,0)
  rect 0.6x2 smd: A1(-41.5,3.6) A2(-40.5,3.6) A3(-39.5,3.6) A4(-38.5,3.6) A5(-37.5,3.6) A6(-36.5,3.6) A7(-35.5,3.6) A8(-34.5,3.6) A9(-33.5,3.6) A10(-32.5,3.6) A11(-31.5,3.6) A12(-28.5,3.6) A13(-27.5,3.6) A14(-26.5,3.6) A15(-25.5,3.6) A16(-24.5,3.6) A17(-23.5,3.6) A18(-22.5,3.6) A19(-21.5,3.6) A20(-20.5,3.6) A21(-19.5,3.6) A22(-18.5,3.6) A23(-17.5,3.6) A24(-16.5,3.6) A25(-15.5,3.6) A26(-14.5,3.6) A27(-13.5,3.6) A28(-12.5,3.6) A29(-11.5,3.6) A30(-10.5,3.6) A31(-9.5,3.6) A32(-8.5,3.6) A33(-7.5,3.6) A34(-6.5,3.6) A35(-5.5,3.6) A36(-4.5,3.6) A37(-3.5,3.6) A38(-2.5,3.6) A39(-1.5,3.6) A40(-0.5,3.6) A41(0.5,3.6) A42(1.5,3.6) A43(2.5,3.6) A44(3.5,3.6) A45(4.5,3.6) A46(5.5,3.6) A47(6.5,3.6) A48(7.5,3.6) A49(8.5,3.6) A50(9.5,3.6) A51(10.5,3.6) A52(11.5,3.6) A53(12.5,3.6) A54(13.5,3.6) A55(14.5,3.6) A56(15.5,3.6) A57(16.5,3.6) A58(17.5,3.6) A59(18.5,3.6) A60(19.5,3.6) A61(20.5,3.6) A62(21.5,3.6) A63(22.5,3.6) A64(23.5,3.6) A65(24.5,3.6) A66(25.5,3.6) A67(26.5,3.6) A68(27.5,3.6) A69(28.5,3.6) A70(29.5,3.6) A71(30.5,3.6) A72(31.5,3.6) A73(32.5,3.6) A74(33.5,3.6) A75(34.5,3.6) A76(35.5,3.6) A77(36.5,3.6) A78(37.5,3.6) A79(38.5,3.6) A80(39.5,3.6) A81(40.5,3.6) A82(41.5,3.6) B1(-41.5,-3.6) B2(-40.5,-3.6) B3(-39.5,-3.6) B4(-38.5,-3.6) B5(-37.5,-3.6) B6(-36.5,-3.6) B7(-35.5,-3.6) B8(-34.5,-3.6) B9(-33.5,-3.6) B10(-32.5,-3.6) B11(-31.5,-3.6) B12(-28.5,-3.6) B13(-27.5,-3.6) B14(-26.5,-3.6) B15(-25.5,-3.6) B16(-24.5,-3.6) B17(-23.5,-3.6) B18(-22.5,-3.6) B19(-21.5,-3.6) B20(-20.5,-3.6) B21(-19.5,-3.6) B22(-18.5,-3.6) B23(-17.5,-3.6) B24(-16.5,-3.6) B25(-15.5,-3.6) B26(-14.5,-3.6) B27(-13.5,-3.6) B28(-12.5,-3.6) B29(-11.5,-3.6) B30(-10.5,-3.6) B31(-9.5,-3.6) B32(-8.5,-3.6) B33(-7.5,-3.6) B34(-6.5,-3.6) B35(-5.5,-3.6) B36(-4.5,-3.6) B37(-3.5,-3.6) B38(-2.5,-3.6) B39(-1.5,-3.6) B40(-0.5,-3.6) B41(0.5,-3.6) B42(1.5,-3.6) B43(2.5,-3.6) B44(3.5,-3.6) B45(4.5,-3.6) B46(5.5,-3.6) B47(6.5,-3.6) B48(7.5,-3.6) B49(8.5,-3.6) B50(9.5,-3.6) B51(10.5,-3.6) B52(11.5,-3.6) B53(12.5,-3.6) B54(13.5,-3.6) B55(14.5,-3.6) B56(15.5,-3.6) B57(16.5,-3.6) B58(17.5,-3.6) B59(18.5,-3.6) B60(19.5,-3.6) B61(20.5,-3.6) B62(21.5,-3.6) B63(22.5,-3.6) B64(23.5,-3.6) B65(24.5,-3.6) B66(25.5,-3.6) B67(26.5,-3.6) B68(27.5,-3.6) B69(28.5,-3.6) B70(29.5,-3.6) B71(30.5,-3.6) B72(31.5,-3.6) B73(32.5,-3.6) B74(33.5,-3.6) B75(34.5,-3.6) B76(35.5,-3.6) B77(36.5,-3.6) B78(37.5,-3.6) B79(38.5,-3.6) B80(39.5,-3.6) B81(40.5,-3.6) B82(41.5,-3.6)
HDR_THVT_1X2_254_871
  rect 2.02x2.02 hole 1.02: 1(0,0)
  round 2.02 hole 1.02: 2(2.54,0)
HDR_THVT_1X3_254_838
  rect 2.02x2.02 hole 1.02: 1(-2.54,0)
  round 2.02 hole 1.02: 2(0,0) 3(2.54,0)
HDR_THVT_1X3_254_871
  rect 2.02x2.02 hole 1.02: 1(-2.54,0)
  round 2.02 hole 1.02: 2(0,0) 3(2.54,0)
HDR_THVT_2X3_254_871
  rect 2.02x2.02 hole 1.02: 1(0,0)
  round 2.02 hole 1.02: 2(2.54,0) 3(0,-2.54) 4(2.54,-2.54) 5(0,-5.08) 6(2.54,-5.08)
HDR_THVT_2X4_254_871
  rect 2.02x2.02 hole 1.02: 1(0,0)
  round 2.02 hole 1.02: 2(2.54,0) 3(0,-2.54) 4(2.54,-2.54) 5(0,-5.08) 6(2.54,-5.08) 7(0,-7.62) 8(2.54,-7.62)
HDR_THVT_2X5_254_838
  rect 2.02x2.02 hole 1.02: 1(0,0)
  round 2.02 hole 1.02: 2(2.54,0) 3(0,-2.54) 4(2.54,-2.54) 5(0,-5.08) 6(2.54,-5.08) 7(0,-7.62) 8(2.54,-7.62) 9(0,-10.16) 10(2.54,-10.16)
IND_SM_DRA73
  rect 2.5x3.25 smd: 1(-3,0) 2(3,0)
LED_0805
  rect 1.19x1.45 smd: 1(-1.045,0) 2(1.045,0)
PW0014AA
  rect 1.6x0.35 smd: 1(-2.8,1.95) 2(-2.8,1.3) 3(-2.8,0.65) 4(-2.8,0) 5(-2.8,-0.65) 6(-2.8,-1.3) 7(-2.8,-1.95) 8(2.8,-1.95) 9(2.8,-1.3) 10(2.8,-0.65) 11(2.8,0) 12(2.8,0.65) 13(2.8,1.3) 14(2.8,1.95)
PW0016AB
  rect 1.5x0.45 smd: 1(-2.9,2.275) 2(-2.9,1.625) 3(-2.9,0.975) 4(-2.9,0.325) 5(-2.9,-0.325) 6(-2.9,-0.975) 7(-2.9,-1.625) 8(-2.9,-2.275) 9(2.9,-2.275) 10(2.9,-1.625) 11(2.9,-0.975) 12(2.9,-0.325) 13(2.9,0.325) 14(2.9,0.975) 15(2.9,1.625) 16(2.9,2.275)
RES_0402
  rect 0.51x0.55 smd: 1(-0.45,0) 2(0.45,0)
RTV0032BA_310X310
  rect 0.6x0.24 smd: 1(-2.4,1.75) 2(-2.4,1.25) 3(-2.4,0.75) 4(-2.4,0.25) 5(-2.4,-0.25) 6(-2.4,-0.75) 7(-2.4,-1.25) 8(-2.4,-1.75) 17(2.4,-1.75) 18(2.4,-1.25) 19(2.4,-0.75) 20(2.4,-0.25) 21(2.4,0.25) 22(2.4,0.75) 23(2.4,1.25) 24(2.4,1.75)
  rect 0.24x0.6 smd: 9(-1.75,-2.4) 10(-1.25,-2.4) 11(-0.75,-2.4) 12(-0.25,-2.4) 13(0.25,-2.4) 14(0.75,-2.4) 15(1.25,-2.4) 16(1.75,-2.4) 25(1.75,2.4) 26(1.25,2.4) 27(0.75,2.4) 28(0.25,2.4) 29(-0.25,2.4) 30(-0.75,2.4) 31(-1.25,2.4) 32(-1.75,2.4)
  rect 3.1x3.1 smd: 33(0,0)
RUA0042BA_205X755
  rect 0.85x0.3 smd: 1(-1.725,4) 2(-1.725,3.5) 3(-1.725,3) 4(-1.725,2.5) 5(-1.725,2) 6(-1.725,1.5) 7(-1.725,1) 8(-1.725,0.5) 9(-1.725,0) 10(-1.725,-0.5) 11(-1.725,-1) 12(-1.725,-1.5) 13(-1.725,-2) 14(-1.725,-2.5) 15(-1.725,-3) 16(-1.725,-3.5) 17(-1.725,-4) 22(1.725,-4) 23(1.725,-3.5) 24(1.725,-3) 25(1.725,-2.5) 26(1.725,-2) 27(1.725,-1.5) 28(1.725,-1) 29(1.725,-0.5) 30(1.725,0) 31(1.725,0.5) 32(1.725,1) 33(1.725,1.5) 34(1.725,2) 35(1.725,2.5) 36(1.725,3) 37(1.725,3.5) 38(1.725,4)
  rect 0.3x0.85 smd: 18(-0.75,-4.475) 19(-0.25,-4.475) 20(0.25,-4.475) 21(0.75,-4.475) 39(0.75,4.475) 40(0.25,4.475) 41(-0.25,4.475) 42(-0.75,4.475)
  rect 2.05x7.55 smd: 43(0,0)
RVF0040BA_330X530
  rect 0.85x0.28 smd: 1(-2.475,2.75) 2(-2.475,2.25) 3(-2.475,1.75) 4(-2.475,1.25) 5(-2.475,0.75) 6(-2.475,0.25) 7(-2.475,-0.25) 8(-2.475,-0.75) 9(-2.475,-1.25) 10(-2.475,-1.75) 11(-2.475,-2.25) 12(-2.475,-2.75) 21(2.475,-2.75) 22(2.475,-2.25) 23(2.475,-1.75) 24(2.475,-1.25) 25(2.475,-0.75) 26(2.475,-0.25) 27(2.475,0.25) 28(2.475,0.75) 29(2.475,1.25) 30(2.475,1.75) 31(2.475,2.25) 32(2.475,2.75)
  rect 0.28x0.85 smd: 13(-1.75,-3.475) 14(-1.25,-3.475) 15(-0.75,-3.475) 16(-0.25,-3.475) 17(0.25,-3.475) 18(0.75,-3.475) 19(1.25,-3.475) 20(1.75,-3.475) 33(1.75,3.475) 34(1.25,3.475) 35(0.75,3.475) 36(0.25,3.475) 37(-0.25,3.475) 38(-0.75,3.475) 39(-1.25,3.475) 40(-1.75,3.475)
  rect 3.3x5.3 smd: 41(0,0)
TANT_3216-18
  rect 1.8x1.23 smd: 1(-1.31,0) 2(1.31,0)
unnamed#2
  round 1.016 smd: (0,0)

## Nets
+3.3V: C70.1 C71.2 C72.2 C73.2 C74.2 C75.2 C76.2 C105.2 J10.1 JMP7.1 JMP8.1 L1.1 L2.1 L3.1 L4.1 L5.1 L6.2 R77.2 R79.1 R80.1 R93.2 R120.1 R131.1 U5.16 U6.40 U7.5 U7.14(VCC)
+3.3VA: J15.B10 J16.B10 P5.B10
+3V: J1.1 J2.1 J3.1 J4.1 J15.A9 J15.A10 J15.B8 J16.A9 J16.A10 J16.B8 P5.A9 P5.A10 P5.B8
+12V: C78.2 C79.2 C80.2 C81.1 C82.2 J11.1 J15.A2 J15.A3 J15.B1 J15.B2 J15.B3 J16.A2 J16.A3 J16.B1 J16.B2 J16.B3 P5.A2 P5.A3 P5.B1 P5.B2 P5.B3 R81.1 U6.21 U6.22 U6.23 U6.24 U6.25 U6.28
GND: C1.1 C2.1 C22.1 C32.1 C37.1 C38.1 C39.1 C40.1 C41.1 C42.1 C43.2 C50.2 C53.2 C60.2 C63.1 C64.1 C65.1 C66.1 C67.1 C68.1 C70.2 C71.1 C72.1 C73.1 C74.1 C75.1 C76.1 C78.1 C79.1 C80.1 C81.2 C82.1 C94.1 C95.1 C96.1 C97.1 C98.1 C99.1 C100.1 C101.1 C102.1 C103.1 C104.1 J10.2 J11.2 J12.2 J12.3 J12.4 J12.5 J12.6 J12.7 J12.8 J12.9 J12.10 J13.2 J13.3 J13.4 J13.5 J13.6 J13.7 J13.8 J13.9 J13.10 J14.2 J14.3 J14.4 J14.5 J14.6 J14.7 J14.8 J14.9 J14.10 J15.A4 J15.A12 J15.A15 J15.A18 J15.A20 J15.A23 J15.A24 J15.A27 J15.A28 J15.A31 J15.A34 J15.A37 J15.A38 J15.A41 J15.A42 J15.A45 J15.A46 J15.A49 J15.A51 J15.A54 J15.A55 J15.A58 J15.A59 J15.A62 J15.A63 J15.A66 J15.A67 J15.A70 J15.A71 J15.A74 J15.A75 J15.A78 J15.A79 J15.A82 J15.B4 J15.B7 J15.B13 J15.B16 J15.B18 J15.B21 J15.B22 J15.B25 J15.B26 J15.B29 J15.B32 J15.B35 J15.B36 J15.B39 J15.B40 J15.B43 J15.B44 J15.B47 J15.B49 J15.B52 J15.B53 J15.B56 J15.B57 J15.B60 J15.B61 J15.B64 J15.B65 J15.B68 J15.B69 J15.B72 J15.B73 J15.B76 J15.B77 J15.B80 J16.A4 J16.A12 J16.A15 J16.A18 J16.A20 J16.A23 J16.A24 J16.A27 J16.A28 J16.A31 J16.A34 J16.A37 J16.A38 J16.A41 J16.A42 J16.A45 J16.A46 J16.A49 J16.A51 J16.A54 J16.A55 J16.A58 J16.A59 J16.A62 J16.A63 J16.A66 J16.A67 J16.A70 J16.A71 J16.A74 J16.A75 J16.A78 J16.A79 J16.A82 J16.B4 J16.B7 J16.B13 J16.B16 J16.B18 J16.B21 J16.B22 J16.B25 J16.B26 J16.B29 J16.B32 J16.B35 J16.B36 J16.B39 J16.B40 J16.B43 J16.B44 J16.B47 J16.B49 J16.B52 J16.B53 J16.B56 J16.B57 J16.B60 J16.B61 J16.B64 J16.B65 J16.B68 J16.B69 J16.B72 J16.B73 J16.B76 J16.B77 J16.B80 J18.6 J19.6 J20.6 J21.6 JMP7.3 JMP8.3 JMP18.3 JMP19.3 JMP20.3 P5.A4 P5.A12 P5.A15 P5.A18 P5.A20 P5.A23 P5.A24 P5.A27 P5.A28 P5.A31 P5.A34 P5.A37 P5.A38 P5.A41 P5.A42 P5.A45 P5.A46 P5.A49 P5.A51 P5.A54 P5.A55 P5.A58 P5.A59 P5.A62 P5.A63 P5.A66 P5.A67 P5.A70 P5.A71 P5.A74 P5.A75 P5.A78 P5.A79 P5.A82 P5.B4 P5.B7 P5.B13 P5.B16 P5.B18 P5.B21 P5.B22 P5.B25 P5.B26 P5.B29 P5.B32 P5.B35 P5.B36 P5.B39 P5.B40 P5.B43 P5.B44 P5.B47 P5.B49 P5.B52 P5.B53 P5.B56 P5.B57 P5.B60 P5.B61 P5.B64 P5.B65 P5.B68 P5.B69 P5.B72 P5.B73 P5.B76 P5.B77 P5.B80 R1.1 R2.1 R3.2 R4.1 R5.1 R6.1 R7.2 R8.1 R9.1 R10.1 R11.2 R12.1 R13.1 R14.1 R15.2 R16.1 R17.1 R18.1 R19.2 R20.1 R21.1 R22.1 R23.2 R24.1 R25.1 R26.1 R27.2 R28.1 R29.1 R30.1 R39.2 R40.1 R41.1 R42.1 R43.2 R44.1 R45.1 R46.1 R47.2 R48.1 R49.1 R50.1 R51.2 R52.1 R53.1 R62.1 R63.2 R64.1 R65.1 R66.1 R67.2 R68.1 R69.1 R70.1 R71.2 R72.1 R73.1 R74.1 R75.2 R76.1 R78.2 R82.2 R83.1 R84.1 R88.2 R89.2 R91.1 R92.1 R94.1 R95.2 R96.2 R97.2 R98.2 R99.2 R100.2 R101.2 R102.2 R103.2 R104.2 R105.2 R106.2 R115.2 R116.2 R117.2 R132.2 R133.1 R134.1 R135.2 R136.1 R137.1 R138.1 R139.2 R140.1 R141.1 R142.1 R143.2 R144.1 R145.1 R146.1 R147.2 R148.1 R149.1 R150.1 R151.2 R152.1 U1.6 U1.9 U1.16 U1.21 U1.30 U1.39 U1.43 U2.6 U2.9 U2.16 U2.21 U2.30 U2.39 U2.43 U3.6 U3.9 U3.16 U3.21 U3.30 U3.39 U3.43 U4.6 U4.9 U4.16 U4.21 U4.30 U4.39 U4.43 U5.4 U5.6 U5.7(VSS) U5.8 U6.13 U6.14 U6.15 U6.16 U6.17 U6.18 U6.19 U6.20 U6.29 U6.30 U6.38 U6.41 U7.7 U7.12 U7.13 U8.1 U8.8 U8.16 U8.17 U8.24 U8.33
VCC0: C37.2 C38.2 C39.2 J1.2 U1.5(VCC#5) U1.13
VCC1: C40.2 C41.2 C42.2 J2.2 U2.5(VCC#5) U2.13
VCC2: C63.2 C64.2 C65.2 J3.2 U3.5(VCC#5) U3.13
VCC3: C66.2 C67.2 C68.2 J4.2 U4.5(VCC#5) U4.13
BP: C104.2 R85.1 R86.1 R87.1 R90.1 U6.31
CLKREQ: C83.1 P5.B12 R125.1 R130.1
EQ0_ADDR_0: JMP1.1 JMP1.3 JMP1.5 JMP1.7 U1.40
EQ0_ADDR_1: JMP4.1 JMP4.3 JMP4.5 JMP4.7 U2.40
EQ0_ADDR_2: JMP9.1 JMP9.3 JMP9.5 JMP9.7 U3.40
EQ0_ADDR_3: JMP14.1 JMP14.3 JMP14.5 JMP14.7 U4.40
EQ1_0: JMP2.1 JMP2.3 JMP2.5 JMP2.7 U1.20
EQ1_1: JMP5.1 JMP5.3 JMP5.5 JMP5.7 U2.20
EQ1_2: JMP10.1 JMP10.3 JMP10.5 JMP10.7 U3.20
EQ1_3: JMP15.1 JMP15.3 JMP15.5 JMP15.7 U4.20
GAIN_SDA_0: J23.1 J23.3 J23.5 J23.7 J23.9 U1.1
GAIN_SDA_1: J25.1 J25.3 J25.5 J25.7 J25.9 U2.1
GAIN_SDA_2: J27.1 J27.3 J27.5 J27.7 J27.9 U3.1
GAIN_SDA_3: J29.1 J29.3 J29.5 J29.7 J29.9 U4.1
JTAG1: J5.3 P5.B9
JTAG1_A: J5.1 J15.B9
JTAG1_B: J5.5 J16.B9
JTAG2: J6.3 P5.A5
JTAG2_A: J6.1 J15.A5
JTAG2_B: J6.5 J16.A5
JTAG3: J7.3 P5.A6
JTAG3_A: J7.1 J15.A6
JTAG3_B: J7.5 J16.A6
JTAG4: J8.3 P5.A7
JTAG4_A: J8.1 J15.A7
JTAG4_B: J8.5 J16.A7
JTAG5: J9.3 P5.A8
JTAG5_A: J9.1 J15.A8
JTAG5_B: J9.5 J16.A8
MODE: R87.2 R89.1 U6.34
MODE_0: JMP3.1 JMP3.3 JMP3.5 JMP3.7 U1.41
MODE_1: JMP6.1 JMP6.3 JMP6.5 JMP6.7 U2.41
MODE_2: JMP11.1 JMP11.3 JMP11.5 JMP11.7 U3.41
MODE_3: JMP16.1 JMP16.3 JMP16.5 JMP16.7 U4.41
PD_0: R35.2 U1.18
PD_1: R36.2 U2.18
PD_2: R37.2 U3.18
PD_3: R38.2 U4.18
PER0_N: J16.A17 P5.A17
PER0_N_A: J15.A17 U3.37
PER0_P: J16.A16 P5.A16
PER0_P_A: J15.A16 U3.38
PER1_N: J16.A22 P5.A22
PER1_N_A: J15.A22 U3.33
PER1_P: J16.A21 P5.A21
PER1_P_A: J15.A21 U3.34
PER2_N: J16.A26 P5.A26
PER2_N_A: J15.A26 U3.28
PER2_P: J16.A25 P5.A25
PER2_P_A: J15.A25 U3.29
PER3_N: J16.A30 P5.A30
PER3_N_A: J15.A30 U3.24
PER3_P: J16.A29 P5.A29
PER3_P_A: J15.A29 U3.25
PER4_N: J16.A36 P5.A36
PER4_N_A: J15.A36 U4.37
PER4_P: J16.A35 P5.A35
PER4_P_A: J15.A35 U4.38
PER5_N: J16.A40 P5.A40
PER5_N_A: J15.A40 U4.33
PER5_P: J16.A39 P5.A39
PER5_P_A: J15.A39 U4.34
PER6_N: J16.A44 P5.A44
PER6_N_A: J15.A44 U4.28
PER6_P: J16.A43 P5.A43
PER6_P_A: J15.A43 U4.29
PER7_N: J16.A48 P5.A48
PER7_N_A: J15.A48 U4.24
PER7_P: J16.A47 P5.A47
PER7_P_A: J15.A47 U4.25
PER8_N: C45.1 P5.A53
PER8_N_B: J16.A53 U3.35
PER8_P: C44.1 P5.A52
PER8_P_B: J16.A52 U3.36
PER9_N: C47.1 P5.A57
PER9_N_B: J16.A57 U3.31
PER9_P: C46.1 P5.A56
PER9_P_B: J16.A56 U3.32
PER10_N: C49.1 P5.A61
PER10_N_B: J16.A61 U3.26
PER10_P: C48.1 P5.A60
PER10_P_B: J16.A60 U3.27
PER11_N: C52.1 P5.A65
PER11_N_B: J16.A65 U3.22
PER11_P: C51.1 P5.A64
PER11_P_B: J16.A64 U3.23
PER12_N: C55.1 P5.A69
PER12_N_B: J16.A69 U4.35
PER12_P: C54.1 P5.A68
PER12_P_B: J16.A68 U4.36
PER13_N: C57.1 P5.A73
PER13_N_B: J16.A73 U4.31
PER13_P: C56.1 P5.A72
PER13_P_B: J16.A72 U4.32
PER14_N: C59.1 P5.A77
PER14_N_B: J16.A77 U4.26
PER14_P: C58.1 P5.A76
PER14_P_B: J16.A76 U4.27
PER15_N: C62.1 P5.A81
PER15_N_B: J16.A81 U4.22
PER15_P: C61.1 P5.A80
PER15_P_B: J16.A80 U4.23
PERST#: J17.3 P5.A11 U7.10
PERST#_A: J17.1 R121.2
PERST#_B: J17.5 R128.2
PERST_INV: J22.2 U7.8
PET0_N: J16.B15 P5.B15
PET0_N_A: C4.2 J15.B15
PET0_P: J16.B14 P5.B14
PET0_P_A: C3.2 J15.B14
PET1_N: J16.B20 P5.B20
PET1_N_A: C8.2 J15.B20
PET1_P: J16.B19 P5.B19
PET1_P_A: C7.2 J15.B19
PET2_N: J16.B24 P5.B24
PET2_N_A: C12.2 J15.B24
PET2_P: J16.B23 P5.B23
PET2_P_A: C11.2 J15.B23
PET3_N: J16.B28 P5.B28
PET3_N_A: C16.2 J15.B28
PET3_P: J16.B27 P5.B27
PET3_P_A: C15.2 J15.B27
PET4_N: J16.B34 P5.B34
PET4_N_A: C20.2 J15.B34
PET4_P: J16.B33 P5.B33
PET4_P_A: C19.2 J15.B33
PET5_N: J16.B38 P5.B38
PET5_N_A: C25.2 J15.B38
PET5_P: J16.B37 P5.B37
PET5_P_A: C24.2 J15.B37
PET6_N: J16.B42 P5.B42
PET6_N_A: C29.2 J15.B42
PET6_P: J16.B41 P5.B41
PET6_P_A: C28.2 J15.B41
PET7_N: J16.B46 P5.B46
PET7_N_A: C34.2 J15.B46
PET7_P: J16.B45 P5.B45
PET7_P_A: C33.2 J15.B45
PET8_N: P5.B51 U1.4
PET8_N_B: C6.2 J16.B51
PET8_P: P5.B50 U1.3
PET8_P_B: C5.2 J16.B50
PET9_N: P5.B55 U1.8
PET9_N_B: C10.2 J16.B55
PET9_P: P5.B54 U1.7
PET9_P_B: C9.2 J16.B54
PET10_N: P5.B59 U1.11
PET10_N_B: C14.2 J16.B59
PET10_P: P5.B58 U1.10
PET10_P_B: C13.2 J16.B58
PET11_N: P5.B63 U1.15
PET11_N_B: C18.2 J16.B63
PET11_P: P5.B62 U1.14
PET11_P_B: C17.2 J16.B62
PET12_N: P5.B67 U2.4
PET12_N_B: C23.2 J16.B67
PET12_P: P5.B66 U2.3
PET12_P_B: C21.2 J16.B66
PET13_N: P5.B71 U2.8
PET13_N_B: C27.2 J16.B71
PET13_P: P5.B70 U2.7
PET13_P_B: C26.2 J16.B70
PET14_N: P5.B75 U2.11
PET14_N_B: C31.2 J16.B75
PET14_P: P5.B74 U2.10
PET14_P_B: C30.2 J16.B74
PET15_N: P5.B79 U2.15
PET15_N_B: C36.2 J16.B79
PET15_P: P5.B78 U2.14
PET15_P_B: C35.2 J16.B78
PGOOD: R90.2 U6.35 U7.2
PRSNT1: J15.A1 J16.A1 P5.A1
PRSNT2_1: C90.1 J18.1 J18.3 J18.5 P5.B17
PRSNT2_1_A: J15.B17 J18.2
PRSNT2_1_B: J16.B17 J18.4
PRSNT2_2: C91.1 J19.1 J19.3 J19.5 P5.B31
PRSNT2_2_A: J15.B31 J19.2
PRSNT2_2_B: J16.B31 J19.4
PRSNT2_3: C92.1 J20.1 J20.3 J20.5 P5.B48
PRSNT2_3_A: J15.B48 J20.2
PRSNT2_3_B: J16.B48 J20.4
PRSNT2_4: C93.1 J21.1 J21.3 J21.5 P5.B81
PRSNT2_4_A: J15.B81 J21.2
PRSNT2_4_B: J16.B81 J21.4
REFCLK_N: P5.A14 R119.2 U8.15
REFCLK_P: P5.A13 R119.1 U8.14
REFCLKA_N: J15.A14 R108.1 R115.1
REFCLKA_P: J15.A13 R106.1 R107.1
REFCLKB_N: J16.A14 R110.1 R117.1
REFCLKB_P: J16.A13 R109.1 R116.1
RSV2: J15.B30 J16.B30
RSVD: C84.1 J15.B82 J16.B82 P5.B82
RSVD1: C85.1 J15.A19 J16.A19 P5.A19
RSVD2: C86.1 P5.B30
RSVD3: C87.1 J15.A32 J16.A32 P5.A32
RSVD4: C88.1 J15.A33 J16.A33 P5.A33
RSVD5: C89.1 J15.A50 J16.A50 P5.A50
RX_DET_SCL_0: J30.1 J30.3 J30.5 J30.7 J30.9 U1.42
RX_DET_SCL_1: J24.1 J24.3 J24.5 J24.7 J24.9 U2.42
RX_DET_SCL_2: J26.1 J26.3 J26.5 J26.7 J26.9 U3.42
RX_DET_SCL_3: J28.1 J28.3 J28.5 J28.7 J28.9 U4.42
SCL: J24.10 J26.10 J28.10 J30.10 R79.2 U5.14
SDA: J23.10 J25.10 J27.10 J29.10 R80.2 U5.15
SEL_0: R31.2 U1.17
SEL_1: R32.2 U2.17
SEL_2: R33.2 U3.17
SEL_3: R34.2 U4.17
SMCLK: P5.B5 R122.1 R126.1
SMDAT: P5.B6 R123.1 R127.1
WAKE: P5.B11(WAKE#) R124.1 R129.1
N16637226: C3.1 U1.38
N16637238: C19.1 U2.38
N16637290: C1.2 U1.2
N16637298: C4.1 U1.37
N16637306: C22.2 U2.2
N16637314: C20.1 U2.37
N16637382: C5.1 U1.36
N16637394: C21.1 U2.36
N16637494: C6.1 U1.35
N16637506: C23.1 U2.35
N16637572: C7.1 U1.34
N16637586: C24.1 U2.34
N16637646: C8.1 U1.33
N16637662: C25.1 U2.33
N16637738: C9.1 U1.32
N16637750: C26.1 U2.32
N16637818: C10.1 U1.31
N16637830: C27.1 U2.31
N16637946: C11.1 U1.29
N16637958: C28.1 U2.29
N16638026: C12.1 U1.28
N16638038: C29.1 U2.28
N16638090: C2.2 U1.12
N16638098: C13.1 U1.27
N16638106: C32.2 U2.12
N16638114: C30.1 U2.27
N16638172: C14.1 U1.26
N16638186: C31.1 U2.26
N16638286: C15.1 U1.25
N16638298: C33.1 U2.25
N16638374: C16.1 U1.24
N16638386: C34.1 U2.24
N16638446: C17.1 U1.23
N16638462: C35.1 U2.23
N16638538: C18.1 U1.22
N16638550: C36.1 U2.22
N16641442: C53.1 U4.2
N16641458: C43.1 U3.2
N16641526: C54.2 U4.3
N16641538: C44.2 U3.3
N16641606: C55.2 U4.4
N16641618: C45.2 U3.4
N16641762: C56.2 U4.7
N16641774: C46.2 U3.7
N16641842: C57.2 U4.8
N16641854: C47.2 U3.8
N16641970: C58.2 U4.10
N16641982: C48.2 U3.10
N16642050: C59.2 U4.11
N16642062: C49.2 U3.11
N16642122: C60.1 U4.12
N16642138: C50.1 U3.12
N16642238: C61.2 U4.14
N16642250: C51.2 U3.14
N16642318: C62.2 U4.15
N16642330: C52.2 U3.15
N16699752: JMP7.2 R31.1 R32.1 R33.1 R34.1
N16699766: J22.1 JMP8.2 R35.1 R36.1 R37.1 R38.1
N16704207: P4.1 U5.12
N16704287: JMP17.1 R77.1
N16704327: P4.9 U5.13
N16704339: JMP17.2 U5.9 U5.10 U5.11
N16704387: JMP17.3 R78.1
N16704399: P4.2 U5.5
N16704407: P4.3 U5.2
N16704427: P4.6 U5.3
N16704435: P4.10 U5.1
N16704743: J5.2 J5.4 J5.6
N16704833: J9.2 J9.4 J9.6
N16704863: J6.2 J6.4 J6.6
N16704881: J7.2 J7.4 J7.6
N16704899: J8.2 J8.4 J8.6
N16707025: R92.2 R93.1 U6.39
N16707333: R86.2 R88.1 U6.33(VSEL)
N16707423: R81.2 R82.1 U6.4
N16707431: R84.2 R85.2 U6.32
N16707493: C69.1 U6.5
N16707501: R91.2 U6.36
N16707563: C69.2 L5.2 U6.8 U6.9 U6.10 U6.11 U6.12
N16708293: C105.1 R132.1 U7.1 U7.4
N16708459: D1.1(CATHODE) R83.2
N16708463: D1.2 U7.3
N16708493: D2.2 U7.6
N16708501: R131.2 U7.9
N16708621: D2.1(CATHODE) R94.2
N16712321: C83.2 R95.1
N16712467: C84.2 R96.1
N16712565: C85.2 R97.1
N16712707: C86.2 R98.1
N16712843: C87.2 R99.1
N16712983: C88.2 R100.1
N16713127: C89.2 R101.1
N16713267: C90.2 R102.1
N16713407: C91.2 R103.1
N16713543: C92.2 R104.1
N16713689: C93.2 R105.1
N16714257: J17.2 J17.4 J17.6
N16716349: C94.2 C95.2 C96.2 C97.2 C98.2 C99.2 C100.2 C101.2 C102.2 C103.2 JMP18.1 JMP19.1 L6.1 U8.2 U8.5 U8.10 U8.20 U8.23 U8.28 U8.30 U8.32(VCC_2)
N16716709: JMP19.2 U8.13
N16716717: JMP18.2 U8.9
N16716953: R107.2 U8.3
N16716991: R108.2 U8.4
N16717029: R109.2 U8.6
N16717077: R110.2 U8.7
N16717223: J13.1 R118.1 U8.27
N16717247: J14.1 R118.2 U8.26
N16717411: J12.1 U8.29
N16717419: JMP20.2 U8.31
N16717493: JMP20.1 R120.2
N16719912: J15.B5 R122.2
N16719964: J15.B6 R123.2
N16720088: J15.A11 R121.1
N16720136: J15.B12 R125.2
N16724044: J16.B5 R126.2
N16724088: J16.B6 R127.2
N16724220: J16.A11 R128.1
N16724224: J16.B11(WAKE#) R129.2
N16724268: J16.B12 R130.2
N16781629: J15.B11(WAKE#) R124.2
N16831338: JMP1.8 R4.2
N16831347: JMP1.6 R3.1
N16831350: JMP1.4 R2.2
N16831359: JMP1.2 R1.2
N16831816: JMP2.8 R8.2
N16831825: JMP2.6 R7.1
N16831828: JMP2.4 R6.2
N16831837: JMP2.2 R5.2
N16831849: JMP3.2 R9.2
N16831858: JMP3.4 R10.2
N16831867: JMP3.6 R11.1
N16831870: JMP3.8 R12.2
N16832723: JMP4.2 R21.2
N16832755: JMP4.4 R22.2
N16832773: JMP4.6 R23.1
N16832779: JMP4.8 R24.2
N16832807: JMP5.2 R25.2
N16832839: JMP5.4 R26.2
N16832857: JMP5.6 R27.1
N16832863: JMP5.8 R28.2
N16832891: JMP6.2 R29.2
N16832923: JMP6.4 R30.2
N16832941: JMP6.6 R39.1
N16832947: JMP6.8 R40.2
N16833662: JMP9.2 R49.2
N16833694: JMP9.4 R50.2
N16833712: JMP9.6 R51.1
N16833718: JMP9.8 R52.2
N16833746: JMP10.2 R53.2
N16833778: JMP10.4 R62.2
N16833796: JMP10.6 R63.1
N16833802: JMP10.8 R64.2
N16833830: JMP11.2 R65.2
N16833862: JMP11.4 R66.2
N16833880: JMP11.6 R67.1
N16833886: JMP11.8 R68.2
N16835436: JMP14.2 R133.2
N16835468: JMP14.4 R134.2
N16835486: JMP14.6 R135.1
N16835492: JMP14.8 R136.2
N16835520: JMP15.2 R137.2
N16835552: JMP15.4 R138.2
N16835570: JMP15.6 R139.1
N16835576: JMP15.8 R140.2
N16835604: JMP16.2 R141.2
N16835636: JMP16.4 R142.2
N16835654: JMP16.6 R143.1
N16835660: JMP16.8 R144.2
N16837171: J30.2 R13.2
N16837180: J30.4 R14.2
N16837189: J30.6 R15.1
N16837198: J30.8 R16.2
N16837577: J23.2 R17.2
N16837609: J23.4 R18.2
N16837629: J23.6 R19.1
N16837647: J23.8 R20.2
N16841214: J24.2 R41.2
N16841246: J24.4 R42.2
N16841266: J24.6 R43.1
N16841284: J24.8 R44.2
N16842142: J25.2 R45.2
N16842174: J25.4 R46.2
N16842194: J25.6 R47.1
N16842212: J25.8 R48.2
N16843638: J26.2 R69.2
N16843670: J26.4 R70.2
N16843690: J26.6 R71.1
N16843708: J26.8 R72.2
N16844326: J27.2 R73.2
N16844358: J27.4 R74.2
N16844378: J27.6 R75.1
N16844396: J27.8 R76.2
N16846395: J28.2 R145.2
N16846427: J28.4 R146.2
N16846447: J28.6 R147.1
N16846465: J28.8 R148.2
N16847091: J29.2 R149.2
N16847123: J29.4 R150.2
N16847143: J29.6 R151.1
N16847161: J29.8 R152.2
N16850880: J1.3 L1.2
N16850966: J2.3 L2.2
N16851615: J3.3 L3.2
N16851807: J4.3 L4.2

Pads without a net: J15 A52 A53 A56 A57 A60 A61 A64 A65 A68 A69 A72 A73 A76 A77 A80 A81 B50 B51 B54 B55 B58 B59 B62 B63 B66 B67 B70 B71 B74 B75 B78 B79; P4 4 5 7 8; U1 19; U2 19; U3 19; U4 19; U6 1 2 3 6 7 26 27 37; U7 11; U8 11 12 18 19 21 22 25

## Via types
v1: diameter 0.508, hole 0.254, TOP to BOTTOM, 1023 vias

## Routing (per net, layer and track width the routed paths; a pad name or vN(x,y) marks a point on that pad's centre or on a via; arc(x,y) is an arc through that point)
+3.3V: length 32.8
  TOP w0.241: U6.40 19.78,80.1 20.08,79.8 27.53,79.8 28.19,80.46 28.19,91.85 27.74,92.3 L5.1 ; R93.2 v1(20.54,78.69)
  TOP w0.305: R80.1 v1(6.45,112.95) ; U7.5 v1(14.69,101.31) ; R79.1 v1(6.45,114.35) ; U5.16 v1(11.09,112.64) ; U7.14 v1(17.29,93.22)
  BOTTOM w0.241: R120.1 v1(7.61,46.08) ; R77.2 v1(26.29,118.11)
  BOTTOM w0.305: C105.2 v1(14.53,96.47) ; R131.1 v1(14.05,93.04)
  vias: v1(4.7,17.4) v1(5.97,17.4) v1(7.24,17.4) v1(8.51,17.4) v1(9.78,17.4) v1(11.05,17.4) v1(12.32,17.4) v1(13.57,73.55) v1(13.57,72.79) v1(13.57,72.03) v1(13.59,17.4) v1(14.33,73.55) v1(14.33,72.79) v1(14.33,72.03) v1(14.86,17.4) v1(15.09,73.55) v1(15.09,72.79) v1(15.09,72.03) v1(16.13,17.4) v1(17.4,17.4) v1(18.67,17.4) v1(19.62,73.6) v1(19.62,72.84) v1(19.62,72.07) v1(19.94,17.4) v1(20.38,73.6) v1(20.38,72.84) v1(20.38,72.07) v1(21.14,73.6) v1(21.14,72.84) v1(21.14,72.07) v1(21.21,17.4) v1(22.48,17.4) v1(23.75,17.4) v1(24.23,101.19) v1(24.23,100.42) v1(24.23,99.66) v1(24.23,98.9) v1(24.99,101.19) v1(24.99,100.42) v1(24.99,99.66) v1(24.99,98.9) v1(25.02,17.4) v1(25.75,101.19) v1(25.75,100.42) v1(25.75,99.66) v1(25.75,98.9) v1(26.29,17.4) v1(27.56,17.4) v1(28.83,17.4) v1(30.1,17.4) v1(31.37,17.4) v1(32.64,17.4) v1(33.91,17.4) v1(35.18,17.4)
+3.3VA:
  vias: v1(55.32,88.82) v1(55.32,87.93) v1(55.32,87.05) v1(55.32,48.18) v1(55.32,47.29) v1(55.32,46.41)
+3V:
  vias: v1(40.23,37.49) v1(40.23,36.47) v1(40.23,35.46) v1(40.23,34.44) v1(41.5,37.49) v1(41.5,36.47) v1(41.5,35.46) v1(41.5,34.44) v1(42.53,101.69) v1(42.53,100.8) v1(42.53,99.91) v1(42.53,61.05) v1(42.53,60.16) v1(42.53,59.27) v1(42.77,37.49) v1(42.77,36.47) v1(42.77,35.46) v1(42.77,34.44) v1(43.42,101.69) v1(43.42,100.8) v1(43.42,99.91) v1(43.42,61.05) v1(43.42,60.16) v1(43.42,59.27) v1(44.04,37.49) v1(44.04,36.47) v1(44.04,35.46) v1(44.04,34.44) v1(45.31,37.49) v1(45.31,36.47) v1(45.31,35.46) v1(45.31,34.44) v1(52.6,15.04) v1(52.6,14.28) v1(52.6,13.57) v1(52.57,12.85) v1(52.58,12.15) v1(52.6,11.45) v1(52.63,8.49)
+12V: length 14.5
  TOP w0.241: 14.62,85.13 14.62,83.83 14.8,83.65 U6.28 ; R81.1 v1(21.83,80.79)
  TOP w0.254: 14.63,85.15 14.62,85.13
  BOTTOM w0.241: v1(21.83,80.79) 15.74,80.79 14.57,81.96 v1(14.57,85.69)
  vias: v1(4.23,82.16) v1(5.12,82.16) v1(6.01,82.16) v1(9.72,84.88) v1(9.72,83.99) v1(9.72,83.1) v1(10.6,84.88) v1(10.6,83.99) v1(10.6,83.1) v1(11.49,84.88) v1(11.49,83.99) v1(11.49,83.1) v1(46.58,89.03) v1(46.58,88.14) v1(46.58,87.25) v1(46.58,48.39) v1(46.58,47.5) v1(46.58,46.61) v1(46.69,10.67) v1(46.69,9.78) v1(46.69,8.89) v1(46.69,8) v1(46.69,7.11) v1(46.69,6.22) v1(47.47,89.03) v1(47.47,88.14) v1(47.47,87.25) v1(47.47,48.39) v1(47.47,47.5) v1(47.47,46.61) v1(47.57,10.67) v1(47.57,9.78) v1(47.57,8.89) v1(47.57,8) v1(47.57,7.11) v1(47.57,6.22) v1(48.36,89.03) v1(48.36,88.14) v1(48.36,87.25) v1(48.36,48.39) v1(48.36,47.5) v1(48.36,46.61)
GND: length 507
  TOP w0.229: C94.1 14.54,57.71 U8.17 ; U8.8 v1(20.75,57.71) ; U8.16 v1(15.9,59.08)
  TOP w0.241: U5.8 v1(16.89,117.19) ; C99.1 20.76,54.12 20.75,54.12 20.66,54.21 U8.1 ; R84.1 v1(15,80.49) ; U5.4 v1(16.89,114.59) ; R92.1 v1(19.88,76.76) ; R91.1 v1(17.65,76.82) ; R104.2 94.19,12.34 93.91,12.06 93.91,11.79 v1(93.85,11.73) ; R101.2 95.95,12.34 95.68,12.07 v1(95.68,11.73) ; C95.1 14.37,54.21 U8.24 ; U6.38 18.78,80.13 v1(18.68,80.03) ; R89.2 v1(16.38,76.82) ; R88.2 v1(15.13,76.82) ; U5.7 v1(16.89,116.54) ; U5.6 v1(16.89,115.89)
  TOP w0.254: v1(101.35,21.03) 100.97,20.65 U1.9 ; U3.30 62.87,22.94 v1(62.48,22.55) ; v1(100.58,22.55) 100.97,22.94 U1.30 ; U4.39 77.45,22.55 v1(78.49,22.55) ; v1(63.25,21.03) 62.87,20.65 U3.9 ; U4.16 85.42,20.96 v1(85.34,21.03) ; v1(81.53,22.55) 81.92,22.94 U4.30 ; U1.16 104.47,20.96 v1(104.39,21.03) ; U4.9 81.92,20.65 v1(82.3,21.03) ; U1.21 105.43,22.55 v1(104.39,22.55) ; U3.6 61.36,20.67 v1(61.72,21.03) ; U1.6 99.46,20.67 v1(99.82,21.03) ; v1(123.44,21.03) 123.52,20.96 U2.16 ; v1(85.34,22.55) 86.38,22.55 U4.21 ; v1(66.29,21.03) 66.37,20.96 U3.16 ; U4.6 80.41,20.67 v1(80.77,21.03) ; U3.21 67.33,22.55 v1(66.29,22.55) ; U2.39 115.55,22.55 v1(116.59,22.55) ; v1(120.4,21.03) 120.02,20.65 U2.9 ; v1(119.63,22.55) 120.02,22.94 U2.30 ; U2.6 118.51,20.67 v1(118.87,21.03) ; U1.39 96.5,22.55 v1(97.54,22.55) ; U3.39 58.4,22.55 v1(59.44,22.55) ; U2.21 124.48,22.55 v1(123.44,22.55)
  TOP w0.305: J16.B80 v1(127.43,48.41) ; J16.A54 101.43,56.08 ; v1(67.07,6.29) 67.62,5.74 P5.B21 ; v1(60.68,11.1) 60.65,11.07 R95.2 ; J16.A42 89.43,56.08 89.43,56.08 ; P5.B43 89.62,5.82 v1(89.11,6.33) ; J16.B61 v1(108.43,48.41) ; P5.B44 90.62,5.84 v1(91.05,6.27) ; R99.2 v1(78.74,12.97) ; J16.A46 93.43,56.08 93.43,56.08 ; v1(78.32,6.54) 78.62,6.25 P5.B32 ; P5.B22 68.62,5.84 v1(69,6.22) ; v1(66.5,11.07) 66.49,11.07 R97.2 ; P5.B29 75.62,5.6 v1(75,6.22) ; P5.B68 114.62,5.9 v1(114.12,6.4) ; U7.7 v1(13.39,98.85) ; R94.1 v1(14.83,108.91) ; J16.B25 v1(72.43,48.41) ; J16.B49 v1(96.43,48.41) ; P5.B40 86.62,5.84 v1(87.07,6.29) ; v1(62.16,6.08) 62.62,5.62 P5.B16 ; J16.B53 v1(100.43,48.41) ; J16.B18 v1(65.43,48.41) ; J15.A45 92.43,96.72 v1(91.79,96.08) ; J16.B26 v1(73.43,48.41) ; J16.B56 v1(103.43,48.41) ; J16.A58 105.43,56.08 ; v1(108.2,6.4) 107.62,5.83 P5.B61 ; J16.B29 v1(76.43,51.25) ; J16.A49 96.43,56.08 ; v1(51.23,6.32) 51.62,5.93 P5.B7 ; P5.B26 72.62,5.84 v1(73.11,6.33) ; v1(59.23,6.43) 59.62,6.04 P5.B13 ; P5.B73 119.62,5.83 v1(120.2,6.4) ; J16.A34 81.43,58.27 v1(81.74,58.57) ; P5.B36 82.62,5.84 v1(83.11,6.33) ; P5.B76 122.62,5.9 v1(122.12,6.4) ; v1(106.12,6.4) 106.62,5.9 P5.B60 ; v1(100.2,6.4) 99.62,5.83 P5.B53 ; P5.B57 103.62,5.83 v1(104.2,6.4) ; J16.B13 v1(60.43,48.41) ; J16.A51 98.43,56.08 98.43,56.08 ; P5.B72 118.62,5.9 v1(118.12,6.4) ; J16.A55 102.43,56.08 102.43,56.08 ; J16.A31 78.43,58.32 v1(78.15,58.6) ; J15.B44 91.43,89.52 ; J16.B32 v1(79.43,48.28) ; P5.B64 110.62,5.9 v1(110.12,6.4) ; v1(98.12,6.4) 98.62,5.9 P5.B52 ; J16.B76 v1(123.43,48.41) ; R103.2 v1(77.47,12.97) ; v1(85.07,6.29) 85.62,5.74 P5.B39 ; J16.B39 v1(86.43,48.41) ; J15.A42 89.43,96.72 v1(90.08,96.08) ; J16.B73 v1(120.43,48.41) ; v1(81.13,12.67) 80.79,12.34 R100.2 ; v1(71.05,6.27) 71.62,5.69 P5.B25 ; R98.2 v1(76.2,12.97) ; v1(126.12,6.4) 126.62,5.9 P5.B80 ; P5.B69 115.62,5.83 v1(116.2,6.4) ; U7.13 v1(16.64,95.74) ; J16.B35 v1(82.43,48.41) ; P5.A49 95.62,6.03 v1(95.66,6.07) ; P5.B77 123.62,5.83 v1(124.2,6.4) ; J16.B52 v1(99.43,48.41) ; J16.B47 v1(94.43,48.41) ; J15.A46 93.43,96.72 v1(94.08,96.08) ; J16.B77 v1(124.43,48.41) ; J16.B64 v1(111.43,48.41) ; P5.A18 64.62,6.01 v1(64.66,6.04) ; v1(102.12,6.4) 102.62,5.9 P5.B56 ; J16.B69 v1(116.43,48.41) ; J16.B65 v1(112.43,48.41) ; J15.B43 90.43,89.52 90.43,89.52 ; J16.B22 v1(69.43,48.41) ; U7.12 v1(15.99,95.72) ; v1(112.2,6.4) 111.62,5.83 P5.B65 ; J16.A45 92.43,56.08 ; J16.B21 v1(68.43,48.41) ; J16.B44 v1(91.43,48.41) ; J16.B72 v1(119.43,48.41) ; v1(93.03,6.25) 93.62,5.65 P5.B47 ; J16.B7 v1(52.43,48.41) ; J16.A59 106.43,56.08 ; 94.43,89.52 94.43,89.52 J15.B47 ; P5.B35 81.62,5.65 v1(81.03,6.25) ; J16.B57 v1(104.43,48.41) ; J16.B40 v1(87.43,48.41) ; J16.A41 88.43,56.08 ; R83.1 v1(16.28,108.89) ; R102.2 v1(63.92,11.05) ; v1(87.79,96.08) 88.43,96.72 J15.A41 ; J16.B60 v1(107.43,48.41) ; J16.B36 v1(83.43,48.41) ; J16.B68 v1(115.43,48.41) ; J16.B4 v1(49.43,51.23) ; J16.B43 v1(90.43,48.41) ; J16.B16 v1(63.43,48.41)
  TOP w0.381: v1(112.79,55.44) 113.43,56.08 J16.A66 ; J16.A34 81.43,56.08 v1(82.08,55.44) ; v1(84.08,88.88) 83.43,89.52 J15.B36 ; J16.A74 121.43,56.08 v1(120.79,55.44) ; J15.A75 v1(122.43,96.25) ; v1(71.79,88.88) 72.43,89.52 J15.B25 ; C96.1 v1(17.32,50.59) ; v1(123.08,55.44) 122.43,56.08 J16.A75 ; J15.A79 v1(126.43,96.25) ; 105.43,56.08 v1(104.79,55.44) ; J16.A27 74.43,56.08 v1(73.79,55.44) ; 106.43,56.08 v1(107.08,55.44) ; v1(76.08,96.08) 75.43,96.72 J15.A28 ; J16.A70 117.43,56.08 v1(116.79,55.44) ; J15.B22 69.43,89.52 v1(70.08,88.88) ; J15.A20 67.43,96.72 v1(68.08,96.08) ; 62.43,96.72 v1(63.08,96.08) ; 62.43,96.72 v1(61.79,96.08) ; 62.43,96.72 J15.A15 ; J15.A66 v1(113.43,96.25) ; J15.B68 v1(115.43,89.05) ; J15.A71 v1(118.43,96.25) ; J15.A78 v1(125.43,96.25) ; C101.1 v1(19.81,60.03) ; v1(108.79,55.44) 109.43,56.08 J16.A62 ; 88.43,56.08 v1(87.79,55.44) ; J15.B52 v1(99.43,89.05) ; v1(82.08,96.08) 81.43,96.72 J15.A34 ; v1(88.08,88.88) 87.43,89.52 J15.B40 ; J15.A67 v1(114.43,96.25) ; J15.B13 60.43,89.52 v1(61.08,88.88) ; 98.43,56.08 v1(99.08,55.44) ; 93.43,56.08 v1(94.08,55.44) ; v1(64.79,55.44) 65.43,56.08 J16.A18 ; J15.B64 v1(111.43,89.05) ; J15.B18 65.43,89.52 v1(66.08,88.88) ; J16.A4 v1(49.43,58.42) ; J15.A54 v1(101.43,96.25) ; J15.B65 v1(112.43,89.05) ; J15.A59 v1(106.43,96.25) ; J15.A38 85.43,96.72 v1(86.08,96.08) ; v1(76.08,55.44) 75.43,56.08 J16.A28 ; 102.43,56.08 v1(103.08,55.44) ; J15.A62 v1(109.43,96.25) ; J15.B73 v1(120.43,89.05) ; J15.A55 v1(102.43,96.25) ; J15.B57 v1(104.43,89.05) ; J15.B60 v1(107.43,89.05) ; v1(95.79,96.08) 96.43,96.72 J15.A49 ; 101.43,56.08 v1(100.79,55.44) ; J15.A4 v1(49.43,96.25) ; J15.A58 v1(105.43,96.25) ; J16.A38 85.43,56.08 v1(86.08,55.44) ; J15.B16 63.43,89.52 v1(62.79,88.88) ; J15.B80 v1(127.43,89.05) ; v1(68.08,55.44) 67.43,56.08 J16.A20 ; J15.A82 v1(129.43,96.25) ; J15.A18 65.43,96.72 v1(64.79,96.08) ; v1(128.79,55.44) 129.43,56.08 J16.A82 ; C97.1 v1(18.53,50.6) ; v1(72.08,96.08) 71.43,96.72 J15.A24 ; 96.43,56.08 v1(95.79,55.44) ; v1(119.08,55.44) 118.43,56.08 J16.A71 ; C99.1 v1(21.81,53.74) ; J16.A12 v1(59.43,55.61) ; R96.2 v1(128.02,12.99) ; 94.43,89.52 v1(93.79,88.88) ; J16.A23 70.43,56.08 v1(69.79,55.44) ; v1(77.79,55.44) 78.43,56.08 J16.A31 ; v1(124.79,55.44) 125.43,56.08 J16.A78 ; J15.A23 70.43,96.72 v1(69.79,96.08) ; v1(75.79,88.88) 76.43,89.52 J15.B29 ; J15.B21 68.43,89.52 v1(67.79,88.88) ; J16.A37 84.43,56.08 v1(83.79,55.44) ; v1(60.08,96.08) 59.43,96.72 J15.A12 ; J15.B72 v1(119.43,89.05) ; 89.43,56.08 v1(90.08,55.44) ; J15.B53 v1(100.43,89.05) ; C100.1 v1(23.02,56.21) ; v1(115.08,55.44) 114.43,56.08 J16.A67 ; v1(63.08,55.44) 62.43,56.08 J16.A15 ; C98.1 v1(19.75,50.6) ; v1(85.79,88.88) 86.43,89.52 J15.B39 ; J15.B76 v1(123.43,89.05) ; v1(111.08,55.44) 110.43,56.08 J16.A63 ; J15.A63 v1(110.43,96.25) ; J15.B4 v1(49.43,89.05) ; 91.43,89.52 v1(92.08,88.88) ; J16.A24 71.43,56.08 v1(72.08,55.44) ; J15.A51 v1(98.43,96.25) ; R82.2 v1(24.75,81.03) ; C95.1 v1(13.52,54.04) ; v1(83.79,96.08) 84.43,96.72 J15.A37 ; J16.A79 126.43,56.08 v1(127.08,55.44) ; J15.B49 v1(96.43,89.05) ; v1(77.79,96.08) 78.43,96.72 J15.A31 ; J15.B69 v1(116.43,89.05) ; J15.B26 73.43,89.52 v1(74.08,88.88) ; C94.1 v1(13.54,57.38) ; J15.A70 v1(117.43,96.25) ; J15.B7 v1(52.43,89.05) ; R105.2 v1(126.75,12.98) ; J15.A27 74.43,96.72 v1(73.79,96.08) ; J15.B56 v1(103.43,89.05) ; 90.43,89.52 v1(89.79,88.88) ; J15.B77 v1(124.43,89.05) ; J15.A74 v1(121.43,96.25) ; v1(81.79,88.88) 82.43,89.52 J15.B35 ; J15.B32 79.43,89.52 v1(80.08,88.88) ; 92.43,56.08 v1(91.79,55.44) ; J15.B61 v1(108.43,89.05)
  BOTTOM w0.241: R76.1 v1(54.99,121.58) ; R64.1 v1(52.96,133.39) ; R53.1 v1(45.34,133.39) ; R22.1 v1(152.53,133.39) ; R28.1 v1(170.69,133.39) ; R74.1 v1(49.91,121.58) ; R8.1 v1(131.44,133.39) ; R6.1 v1(126.36,133.39) ; R50.1 v1(34.8,133.39) ; R70.1 v1(65.53,121.58) ; R14.1 v1(128.02,121.58) ; R49.1 v1(32.26,133.39) ; R7.2 v1(128.91,133.39) ; R62.1 v1(47.88,133.39) ; R51.2 v1(37.34,133.39) ; R2.1 v1(113.28,133.39) ; R23.2 v1(155.07,133.39) ; R12.1 v1(144.53,133.39) ; R24.1 v1(157.61,133.39) ; R48.1 v1(148.72,121.58) ; R10.1 v1(139.45,133.39) ; R63.2 v1(50.42,133.39) ; R11.2 v1(141.99,133.39) ; R9.1 v1(136.91,133.39) ; R45.1 v1(141.1,121.58) ; R17.1 v1(109.86,121.58) ; R39.2 v1(181.23,133.39) ; R78.2 v1(26.17,113.03) ; R73.1 v1(47.37,121.58) ; R16.1 v1(133.1,121.58) ; R67.2 v1(63.5,133.39) ; R42.1 v1(159.26,121.58) ; R52.1 v1(39.88,133.39) ; R4.1 v1(118.36,133.39) ; R15.2 v1(130.56,121.58) ; R3.2 v1(115.82,133.39) ; R1.1 v1(110.74,133.39) ; R13.1 v1(125.48,121.58) ; R5.1 v1(123.83,133.39) ; R18.1 v1(112.39,121.58) ; R30.1 v1(178.69,133.39)
  BOTTOM w0.305: R138.1 v1(87.12,133.43) ; P5.A45 91.62,5.69 v1(91.05,6.27) ; C22.1 117.71,20.66 v1(117.35,21.03) ; P5.A79 125.62,5.9 v1(126.12,6.4) ; v1(121.92,21.03) 122.15,20.8 C32.1 ; v1(83.82,21.03) 84.21,20.65 C60.2 ; P5.A12 58.62,5.82 v1(59.23,6.43) ; R147.2 v1(99.31,121.61) ; R43.2 v1(161.8,121.58) ; v1(71.05,6.27) 70.62,5.84 P5.A24 ; P5.A46 92.62,5.84 v1(93.03,6.25) ; R133.1 v1(71.5,133.43) ; R71.2 v1(68.07,121.58) ; P5.A78 124.62,5.98 v1(124.2,6.4) ; R146.1 v1(96.77,121.61) ; P5.A70 116.62,5.98 v1(116.2,6.4) ; v1(78.32,6.54) 77.62,5.84 P5.A31 ; R132.2 v1(15.77,96.44) ; v1(89.11,6.33) 88.62,5.85 P5.A42 ; C2.1 103.28,20.62 v1(102.87,21.03) ; R66.1 v1(60.96,133.39) ; R143.2 v1(102.74,133.43) ; R135.2 v1(76.58,133.43) ; v1(85.07,6.29) 84.62,5.84 P5.A38 ; R29.1 v1(176.15,133.39) ; v1(112.2,6.4) 112.62,5.98 P5.A66 ; v1(64.01,21.03) 63.62,20.65 C50.2 ; P5.A34 80.62,5.84 v1(81.03,6.25) ; v1(122.12,6.4) 121.62,5.9 P5.A75 ; v1(24.34,54.27) 24.5,54.43 R106.2 ; R116.2 24.5,57.23 v1(24.34,57.06) ; 60.28,20.95 v1(60.2,21.03) ; R137.1 v1(84.58,133.43) ; R148.1 v1(101.85,121.61) ; v1(95.66,6.07) 95.62,6.03 P5.A49 ; v1(67.07,6.29) 66.62,5.84 P5.A20 ; R149.1 v1(78.61,121.61) ; R68.1 v1(66.04,133.39) ; R21.1 v1(149.99,133.39) ; R115.2 24.5,55.7 v1(24.34,55.86) ; R140.1 v1(92.2,133.43) ; P5.A28 74.62,5.84 v1(75,6.22) ; P5.A41 87.62,5.74 v1(87.07,6.29) ; R151.2 v1(83.69,121.61) ; R142.1 v1(100.2,133.43) ; v1(108.2,6.4) 108.62,5.98 P5.A62 ; R27.2 v1(168.15,133.39) ; R41.1 v1(156.72,121.58) ; v1(127.97,6.29) 128.62,5.63 P5.A82 ; R47.2 v1(146.18,121.58) ; R20.1 v1(117.47,121.58) ; v1(64.66,6.04) 64.62,6.01 P5.A18 ; v1(102.12,6.4) 101.62,5.9 P5.A55 ; v1(73.11,6.33) 73.62,5.83 P5.A27 ; R144.1 v1(105.28,133.43) ; P5.A37 83.62,5.83 v1(83.11,6.33) ; v1(104.2,6.4) 104.62,5.98 P5.A58 ; C1.1 98.46,20.87 v1(98.3,21.03) ; P5.A74 120.62,5.98 v1(120.2,6.4) ; R40.1 v1(183.77,133.39) ; v1(60.96,21.03) 60.77,20.84 C43.2 ; R150.1 v1(81.15,121.61) ; v1(110.12,6.4) 109.62,5.9 P5.A63 ; R65.1 v1(58.42,133.39) ; v1(62.16,6.08) 61.62,5.54 P5.A15 ; R25.1 v1(163.07,133.39) ; R75.2 v1(52.45,121.61) ; R46.1 v1(143.64,121.58) ; v1(24.34,58.66) 24.5,58.5 R117.2 ; P5.A67 113.62,5.9 v1(114.12,6.4) ; C53.2 79.54,20.74 v1(79.25,21.03) ; P5.A54 100.62,5.98 v1(100.2,6.4) ; R134.1 v1(74.04,133.43) ; v1(69,6.22) 69.62,5.6 P5.A23 ; R145.1 v1(94.23,121.61) ; P5.A71 117.62,5.9 v1(118.12,6.4) ; R19.2 v1(114.94,121.58) ; R141.1 v1(97.66,133.43) ; R44.1 v1(164.34,121.58) ; P5.A59 105.62,5.9 v1(106.12,6.4) ; R26.1 v1(165.61,133.39) ; P5.A51 97.62,5.9 v1(98.12,6.4) ; R72.1 v1(70.61,121.58) ; R136.1 v1(79.12,133.43) ; R69.1 v1(62.99,121.58) ; R152.1 v1(86.23,121.61) ; R139.2 v1(89.66,133.43)
  vias: v1(7.98,89.14) v1(8.74,89.14) v1(9.5,89.14) v1(10.27,89.14) v1(11.12,104.93) v1(11.61,89.16) v1(12.37,89.16) v1(13.14,89.16) v1(13.9,89.16) v1(16.49,57.18) v1(16.49,56.42) v1(16.49,55.66) v1(16.49,54.89) v1(16.87,86.7) v1(16.87,85.94) v1(16.87,85.17) v1(16.87,84.41) v1(16.87,83.65) v1(16.87,82.89) v1(16.87,82.13) v1(17.26,57.18) v1(17.26,56.42) v1(17.26,55.66) v1(17.26,54.89) v1(17.63,86.7) v1(17.63,85.94) v1(17.63,85.17) v1(17.63,84.41) v1(17.63,83.65) v1(17.63,82.89) v1(17.63,82.13) v1(18.02,57.18) v1(18.02,56.42) v1(18.02,55.66) v1(18.02,54.89) v1(18.39,86.7) v1(18.39,85.94) v1(18.39,85.17) v1(18.39,84.41) v1(18.39,83.65) v1(18.39,82.89) v1(18.39,82.13) v1(18.78,57.18) v1(18.78,56.42) v1(18.78,55.66) v1(18.78,54.89) v1(19.16,86.7) v1(19.16,85.94) v1(19.16,85.17) v1(19.16,84.41) v1(19.16,83.65) v1(19.16,82.89) v1(19.16,82.13) v1(19.43,63) v1(19.59,63.63) v1(19.92,64.65) v1(20.26,63.89) v1(20.26,62.97) v1(21.21,97.8) v1(21.24,97.1) v1(21.4,101.17) v1(21.4,99.83) v1(21.4,98.5) v1(21.4,95.83) v1(21.4,94.5) v1(28.29,100.75) v1(28.29,99.42) v1(28.37,95.48) v1(28.43,94.52) v1(28.93,98.01) v1(28.95,97.11) v1(48.67,6.93) v1(48.66,6.18) v1(56.68,26.16) v1(58.2,28.06) v1(58.39,26.16) v1(58.75,14.51) v1(59.44,21.79) v1(59.44,21.03) v1(59.73,26.16) v1(59.92,28.06) v1(60.2,22.55) v1(60.2,21.79) v1(60.78,13.62) v1(60.88,14.51) v1(60.96,22.55) v1(60.96,21.79) v1(61.26,28.06) v1(61.44,26.16) v1(61.72,22.55) v1(61.72,21.79) v1(62.48,21.79) v1(62.48,21.03) v1(62.76,26.16) v1(62.81,14.51) v1(62.92,13.62) v1(62.97,28.06) v1(63.25,22.55) v1(63.25,21.79) v1(64.01,22.55) v1(64.01,21.79) v1(64.29,28.06) v1(64.47,26.16) v1(64.77,22.55) v1(64.77,21.79) v1(64.77,21.03) v1(64.85,13.62) v1(64.95,14.51) v1(65.53,22.55) v1(65.53,21.79) v1(65.53,21.03) v1(65.81,26.16) v1(66,28.06) v1(66.29,21.79) v1(66.98,13.62) v1(67.34,28.06) v1(67.53,26.16) v1(68.93,21.87) v1(69.04,22.55) v1(69.05,28.06) v1(69.56,21.89) v1(74.84,20.01) v1(75.73,26.16) v1(75.92,21.54) v1(77.25,28.06) v1(77.44,26.16) v1(77.8,14.51) v1(78.49,21.79) v1(78.49,21.03) v1(78.78,26.16) v1(78.97,28.06) v1(79.25,22.55) v1(79.25,21.79) v1(79.88,14.5) v1(80.01,22.55) v1(80.01,21.79) v1(80.01,21.03) v1(80.31,28.06) v1(80.49,26.16) v1(80.77,22.55) v1(80.77,21.79) v1(81.53,21.79) v1(81.53,21.03) v1(81.81,26.16) v1(81.92,14.5) v1(82.02,28.06) v1(82.3,22.55) v1(82.3,21.79) v1(83.06,22.55) v1(83.06,21.79) v1(83.06,21.03) v1(83.34,28.06) v1(83.52,26.16) v1(83.82,22.55) v1(83.82,21.79) v1(83.95,14.5) v1(84.58,22.55) v1(84.58,21.79) v1(84.58,21.03) v1(84.86,26.16) v1(85.05,28.06) v1(85.34,21.79) v1(86,14.5) v1(86.39,28.06) v1(86.58,26.16) v1(88.1,28.06) v1(88.09,22.55) v1(88.08,21.89) v1(88.74,21.89) v1(92.81,30.11) v1(94.95,30.11) v1(94.96,21.5) v1(95,20.01) v1(95.68,18.97) v1(96.88,30.11) v1(97.54,21.79) v1(97.54,21.03) v1(98.3,22.55) v1(98.3,21.79) v1(99.01,30.11) v1(99.06,22.55) v1(99.06,21.79) v1(99.06,21.03) v1(99.82,22.55) v1(99.82,21.79) v1(100.58,21.79) v1(100.58,21.03) v1(100.94,30.11) v1(101.35,22.55) v1(101.35,21.79) v1(102.11,22.55) v1(102.11,21.79) v1(102.11,21.03) v1(102.87,22.55) v1(102.87,21.79) v1(103.07,30.11) v1(103.63,22.55) v1(103.63,21.79) v1(103.63,21.03) v1(104.39,21.79) v1(105,30.11) v1(107.14,30.11) v1(107.14,22.55) v1(108.19,21.39) v1(108.26,20.59) v1(111.69,20.75) v1(111.86,30.11) v1(112.6,21.54) v1(114,30.11) v1(114.02,21.54) v1(115.93,30.11) v1(116.59,21.79) v1(116.59,21.03) v1(117.35,22.55) v1(117.35,21.79) v1(118.06,30.11) v1(118.11,22.55) v1(118.11,21.79) v1(118.11,21.03) v1(118.87,22.55) v1(118.87,21.79) v1(119.63,21.79) v1(119.63,21.03) v1(119.99,30.11) v1(120.4,22.55) v1(120.4,21.79) v1(121.16,22.55) v1(121.16,21.79) v1(121.16,21.03) v1(121.92,22.55) v1(121.92,21.79) v1(122.12,30.11) v1(122.68,22.55) v1(122.68,21.79) v1(122.68,21.03) v1(123.44,21.79) v1(124.05,30.11) v1(125.3,22.72) v1(126.19,30.11) v1(127.25,21.18) v1(127.23,20.51)
